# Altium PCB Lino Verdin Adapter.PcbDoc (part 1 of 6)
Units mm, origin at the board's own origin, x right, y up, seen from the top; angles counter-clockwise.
Board outline 69.6 x 35 mm, 8 copper layers (Top Layer, Mid 1, GND 1, Mid 2, Mid 3, GND 2, Mid 4, Bottom Layer), stack 1.198 mm thick; 208 components, 258 nets, 1063 pads, 1090 vias.
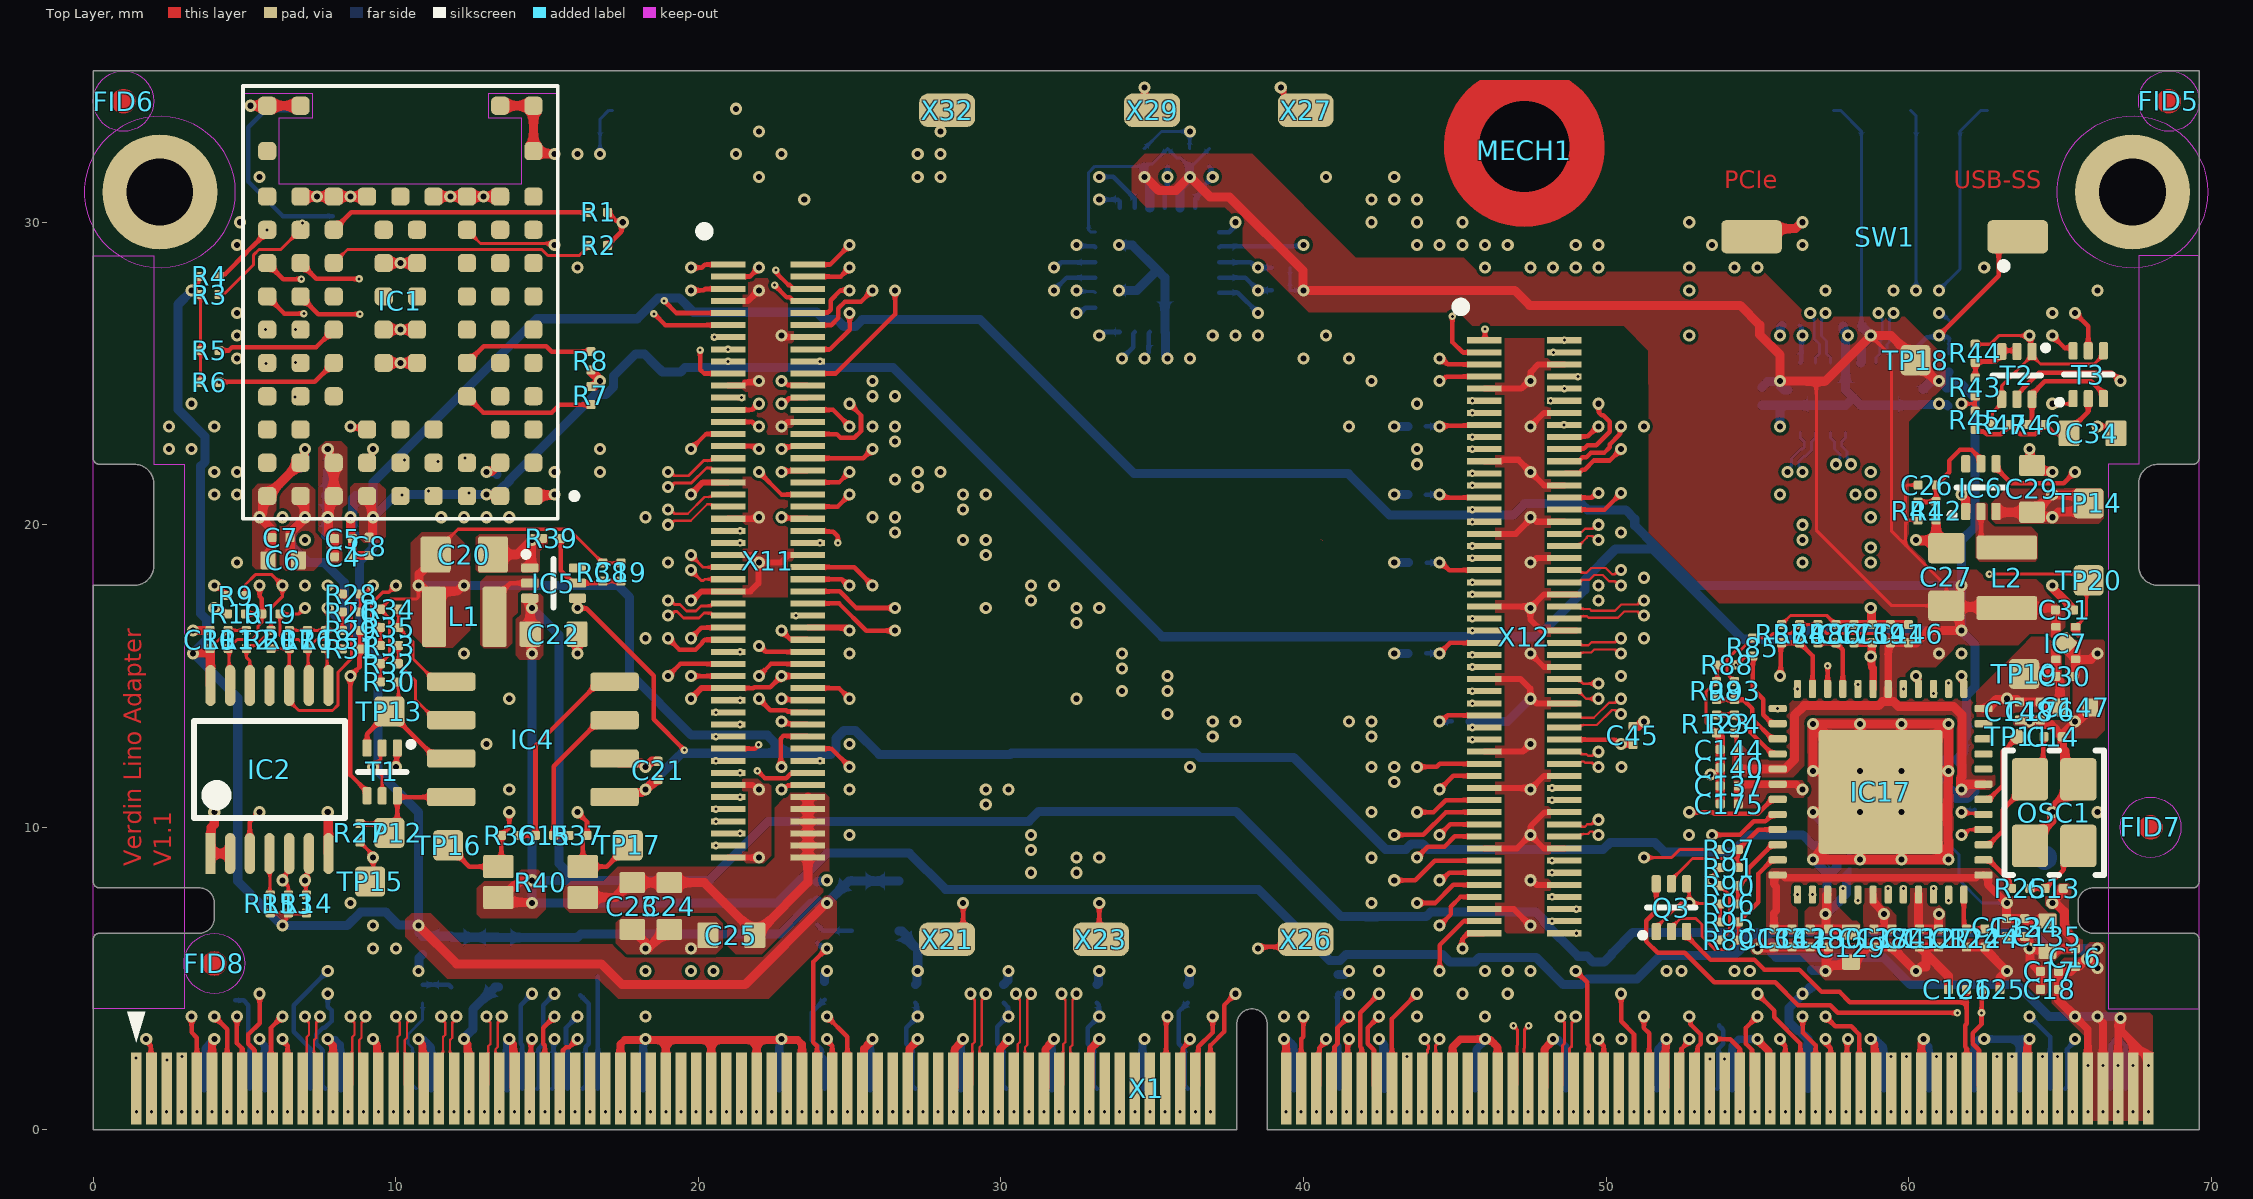
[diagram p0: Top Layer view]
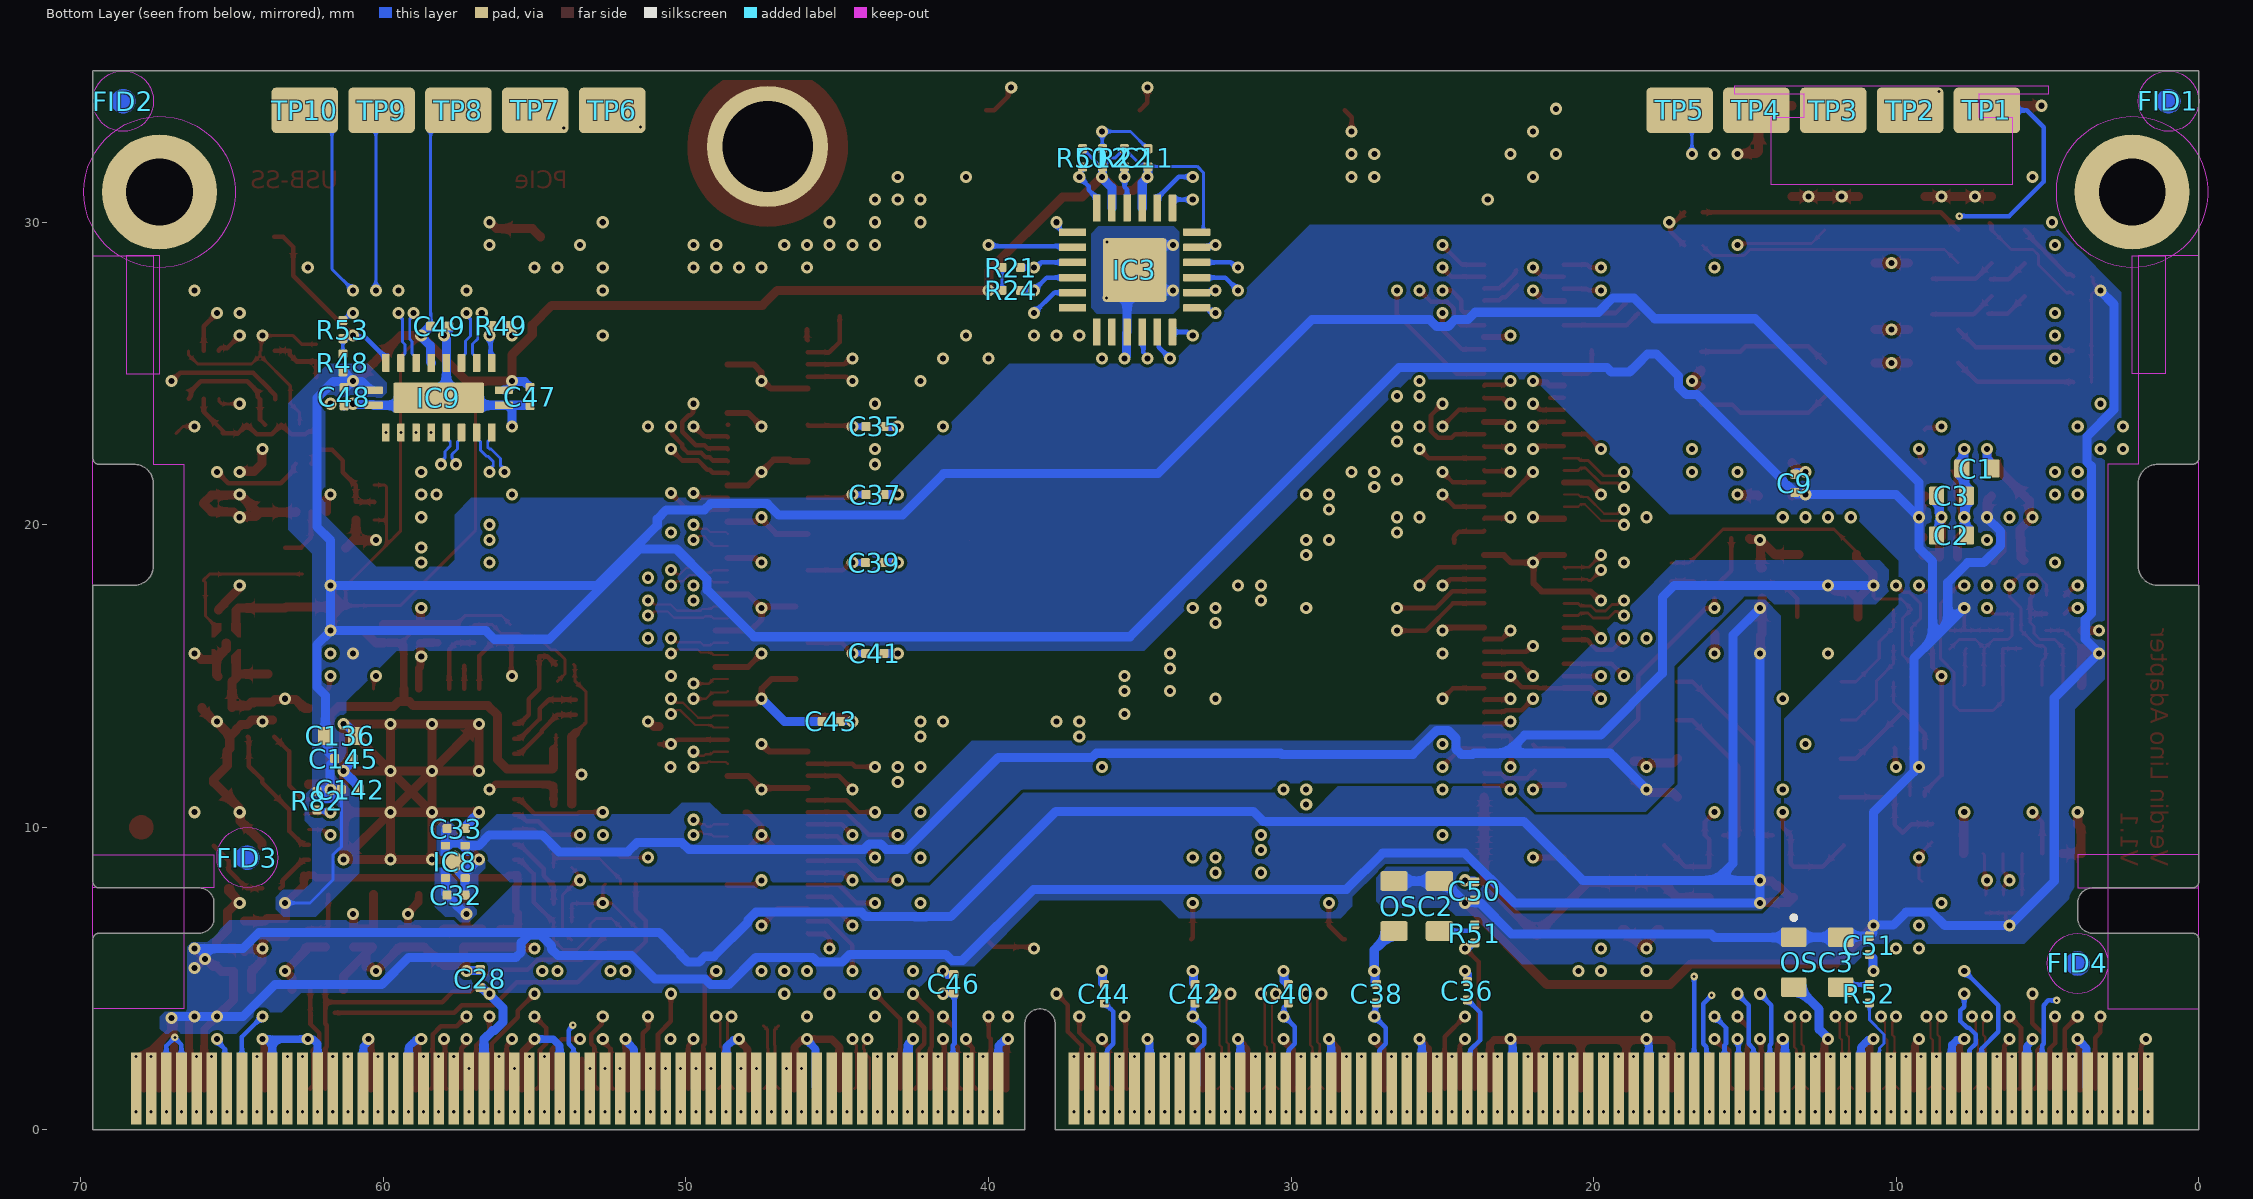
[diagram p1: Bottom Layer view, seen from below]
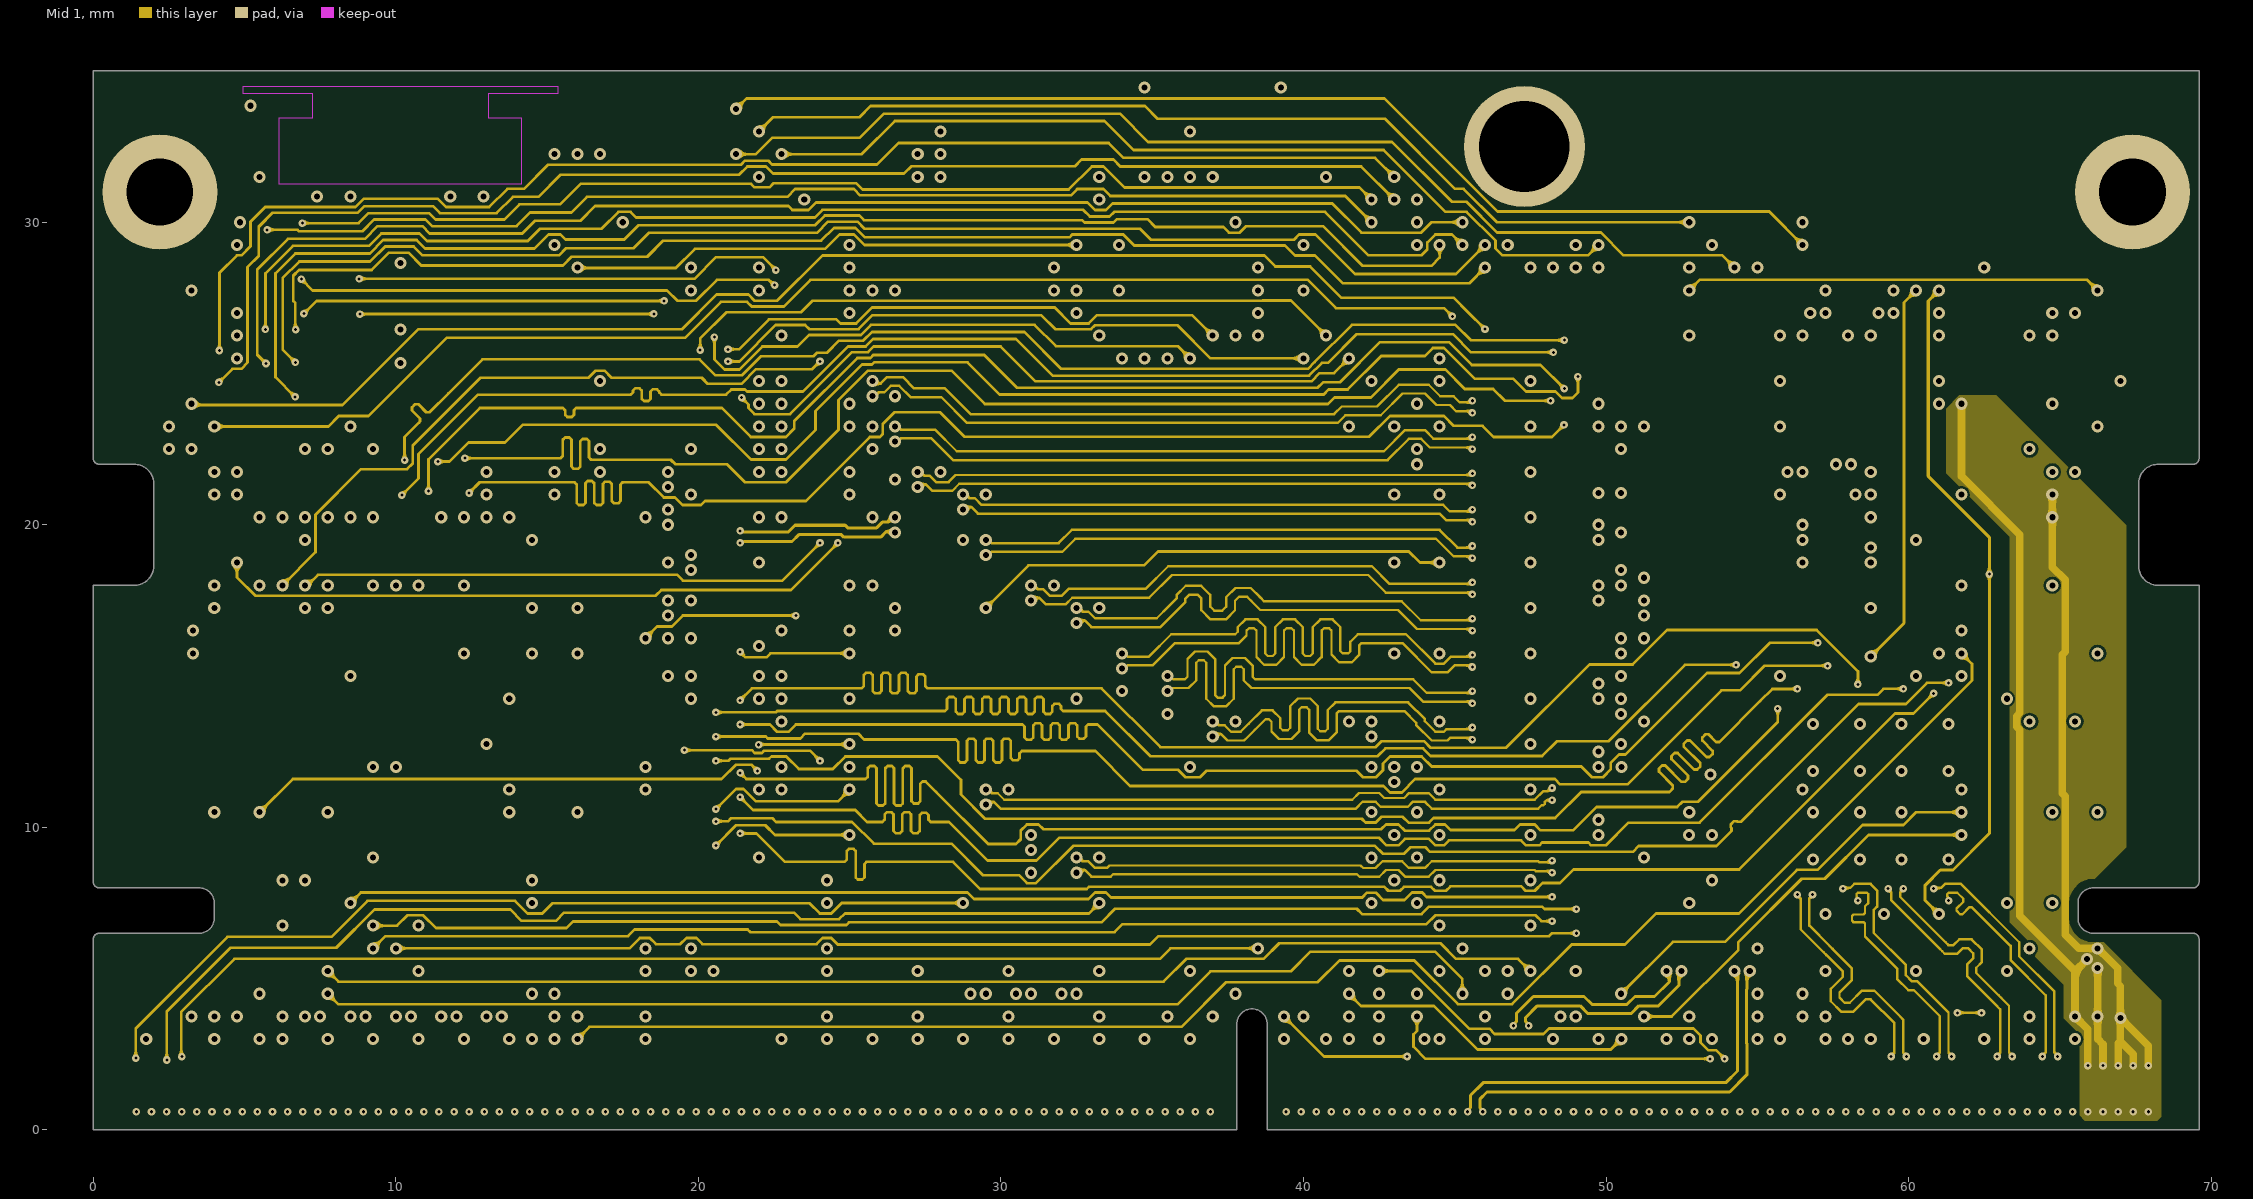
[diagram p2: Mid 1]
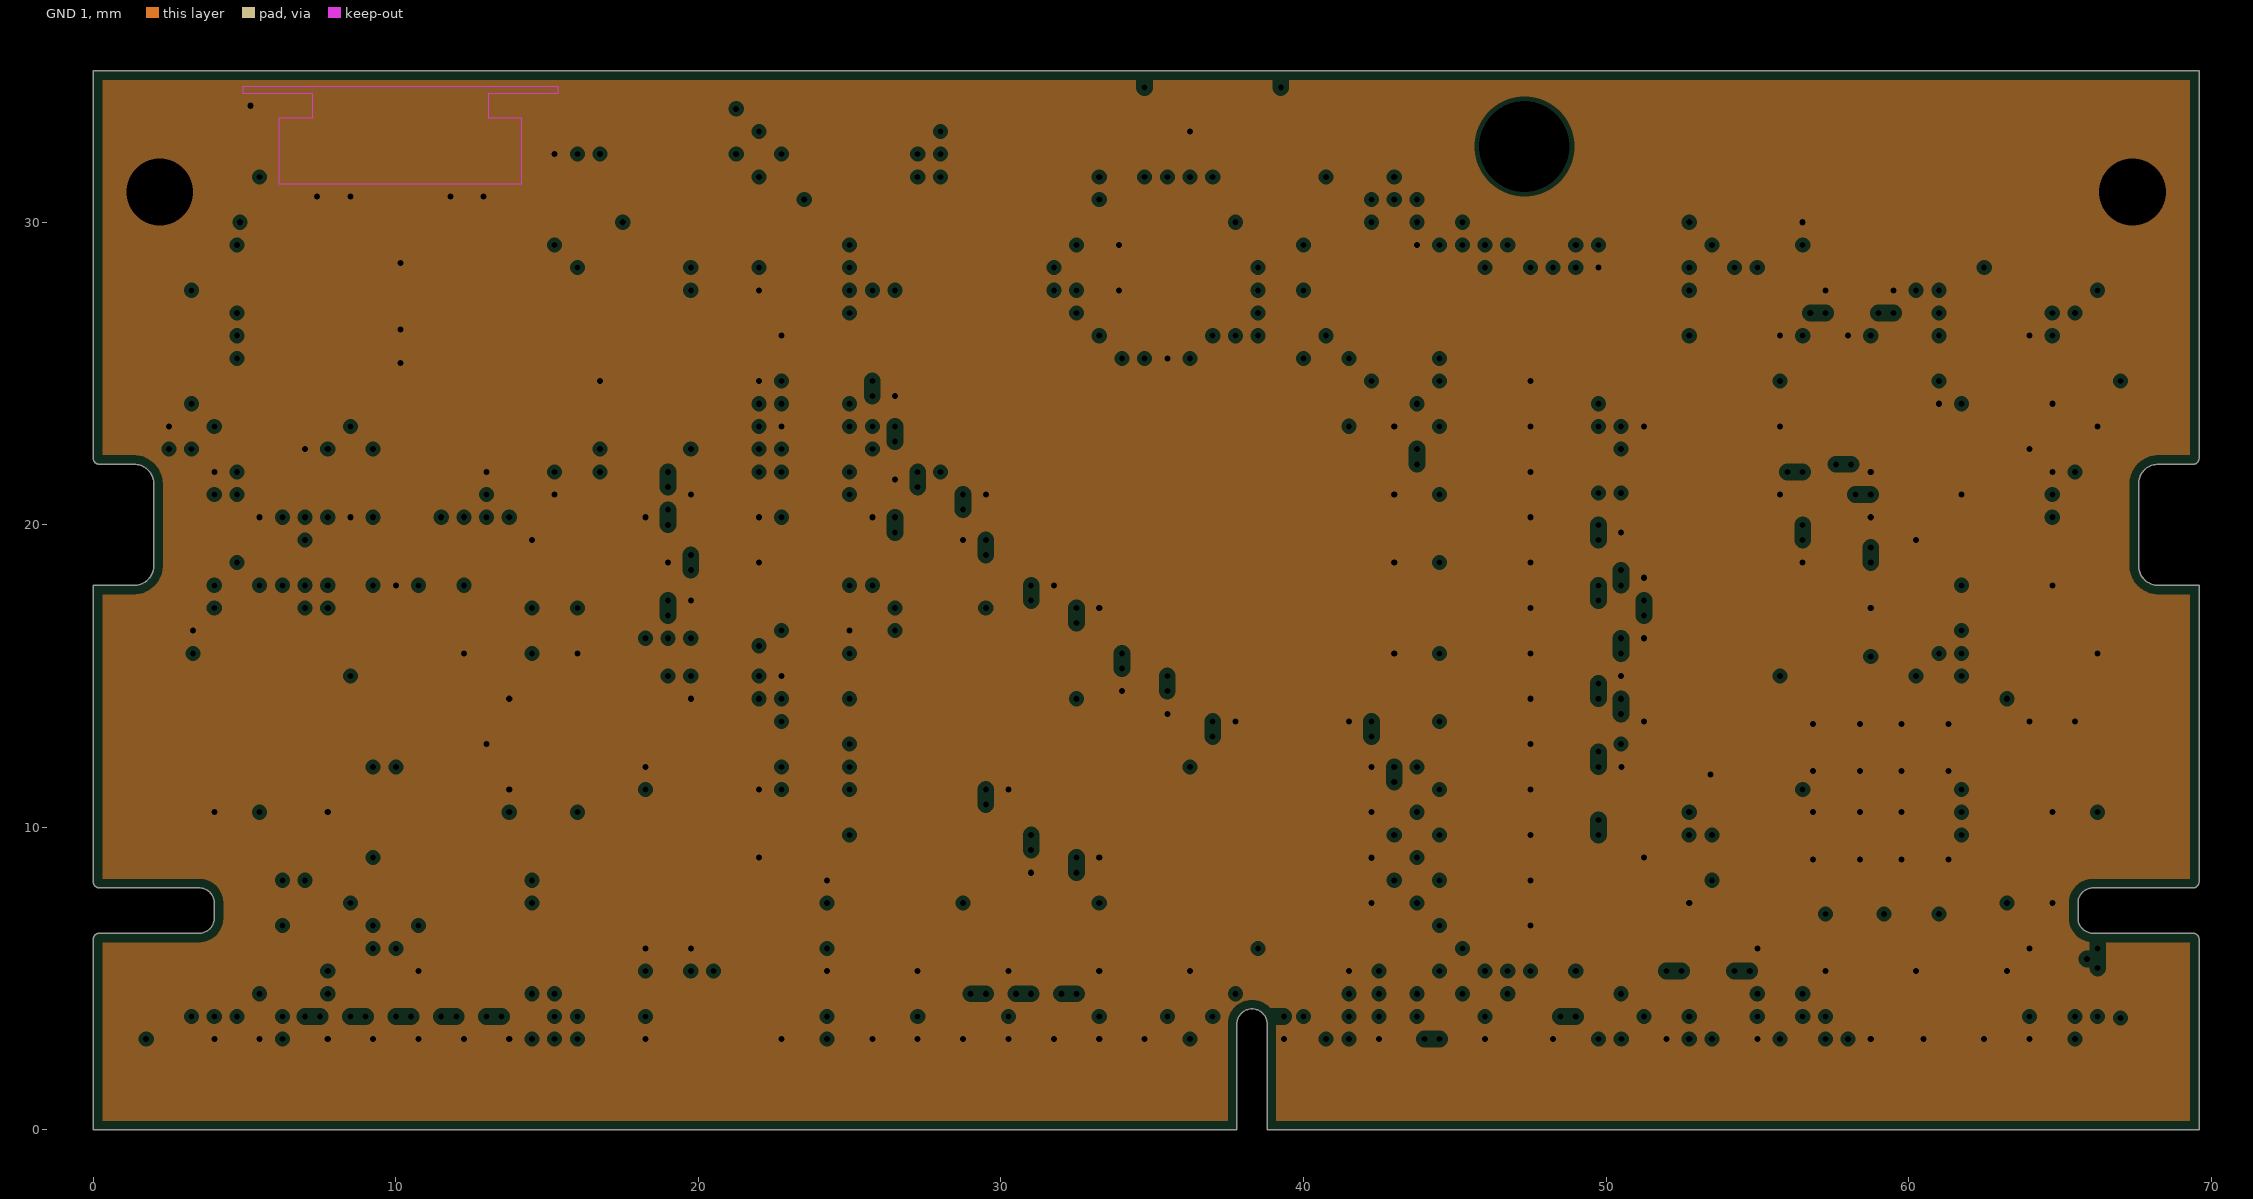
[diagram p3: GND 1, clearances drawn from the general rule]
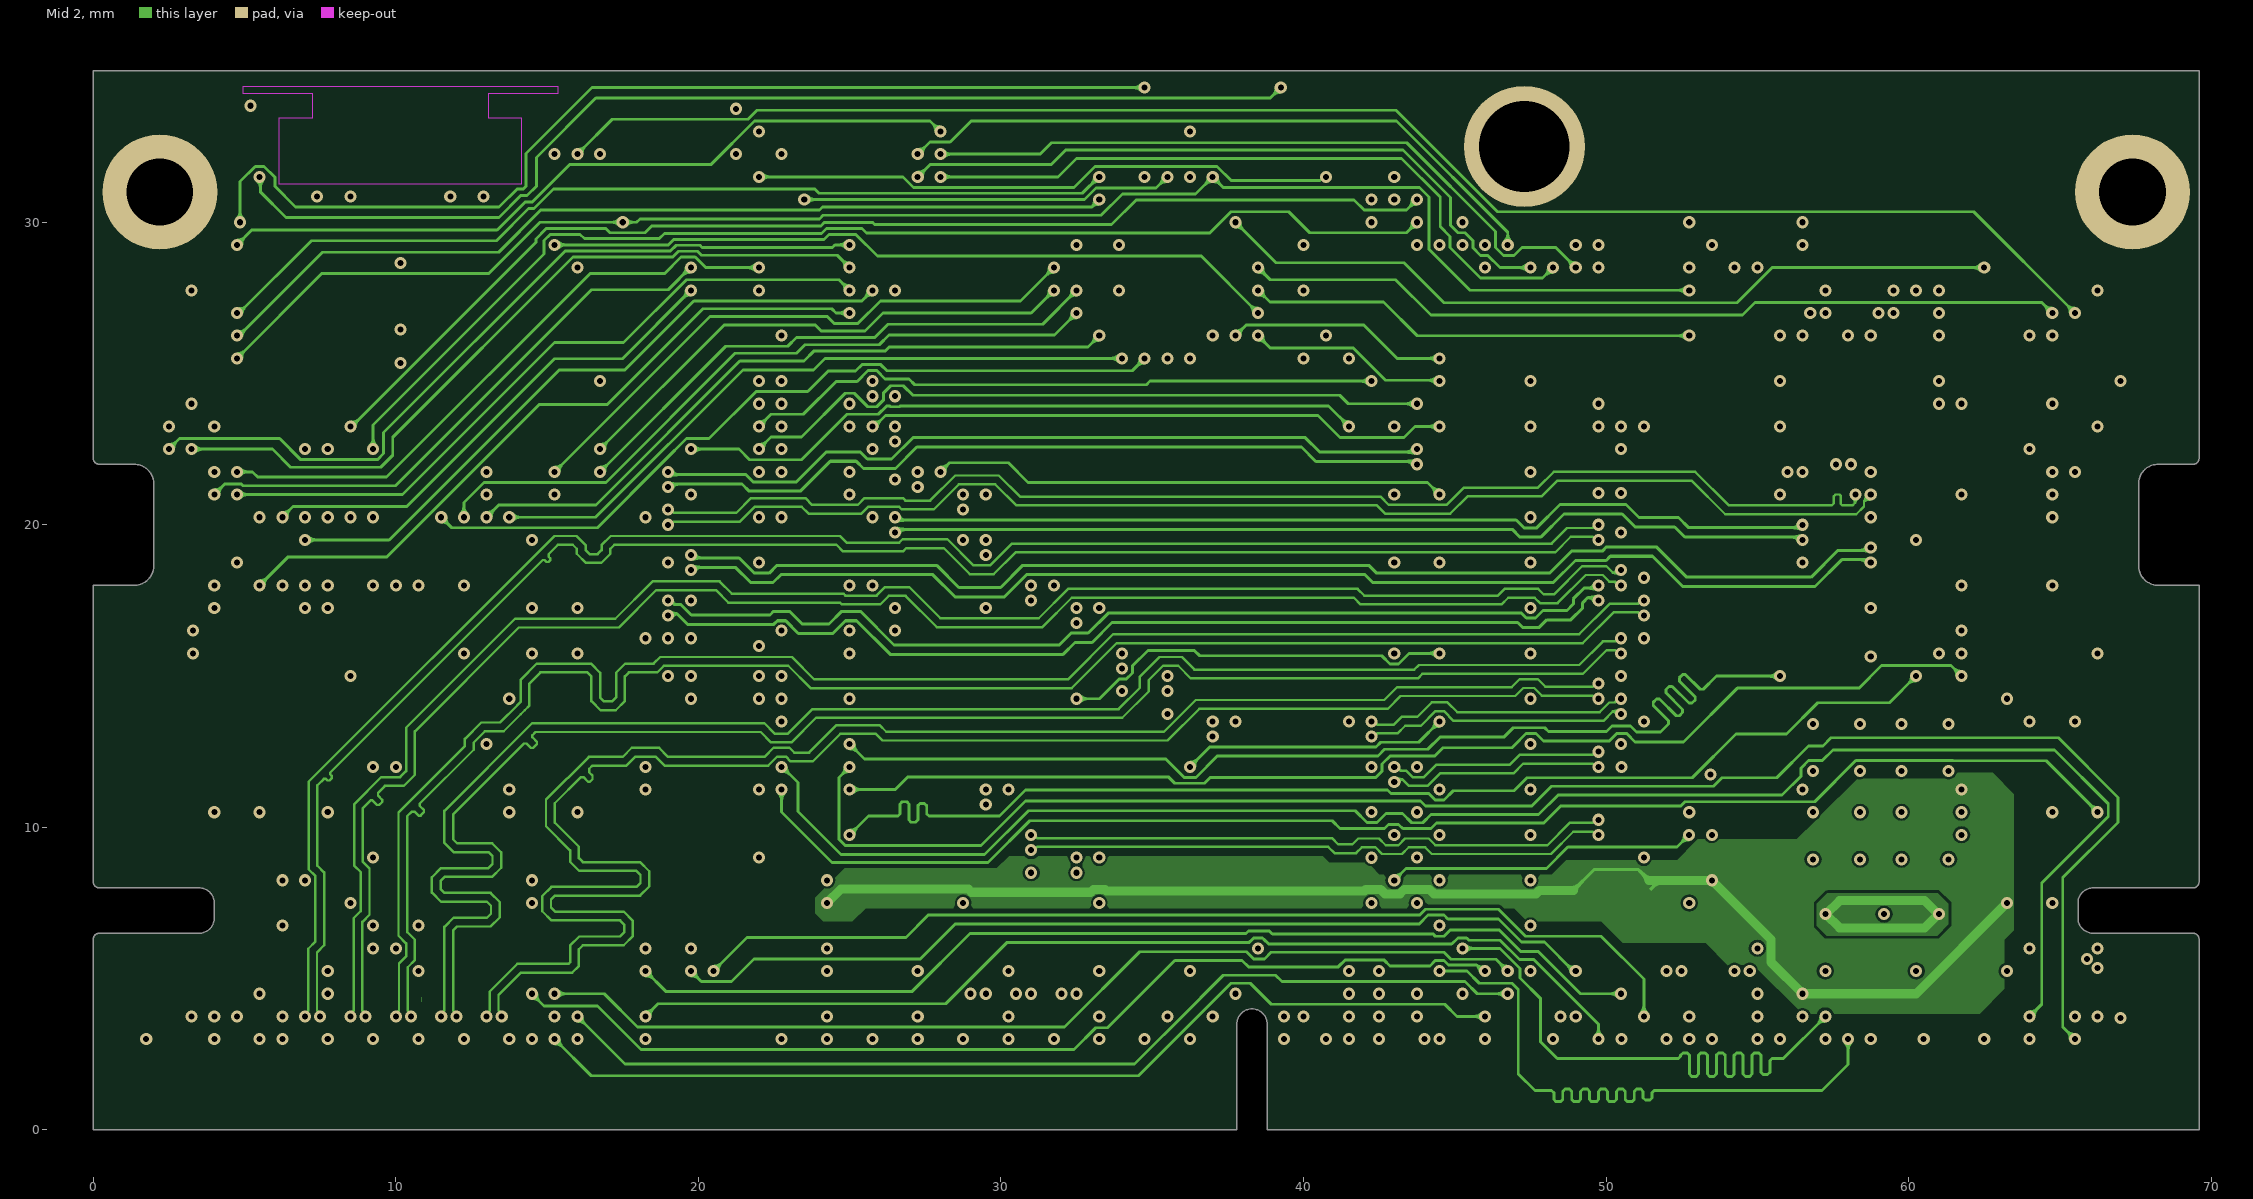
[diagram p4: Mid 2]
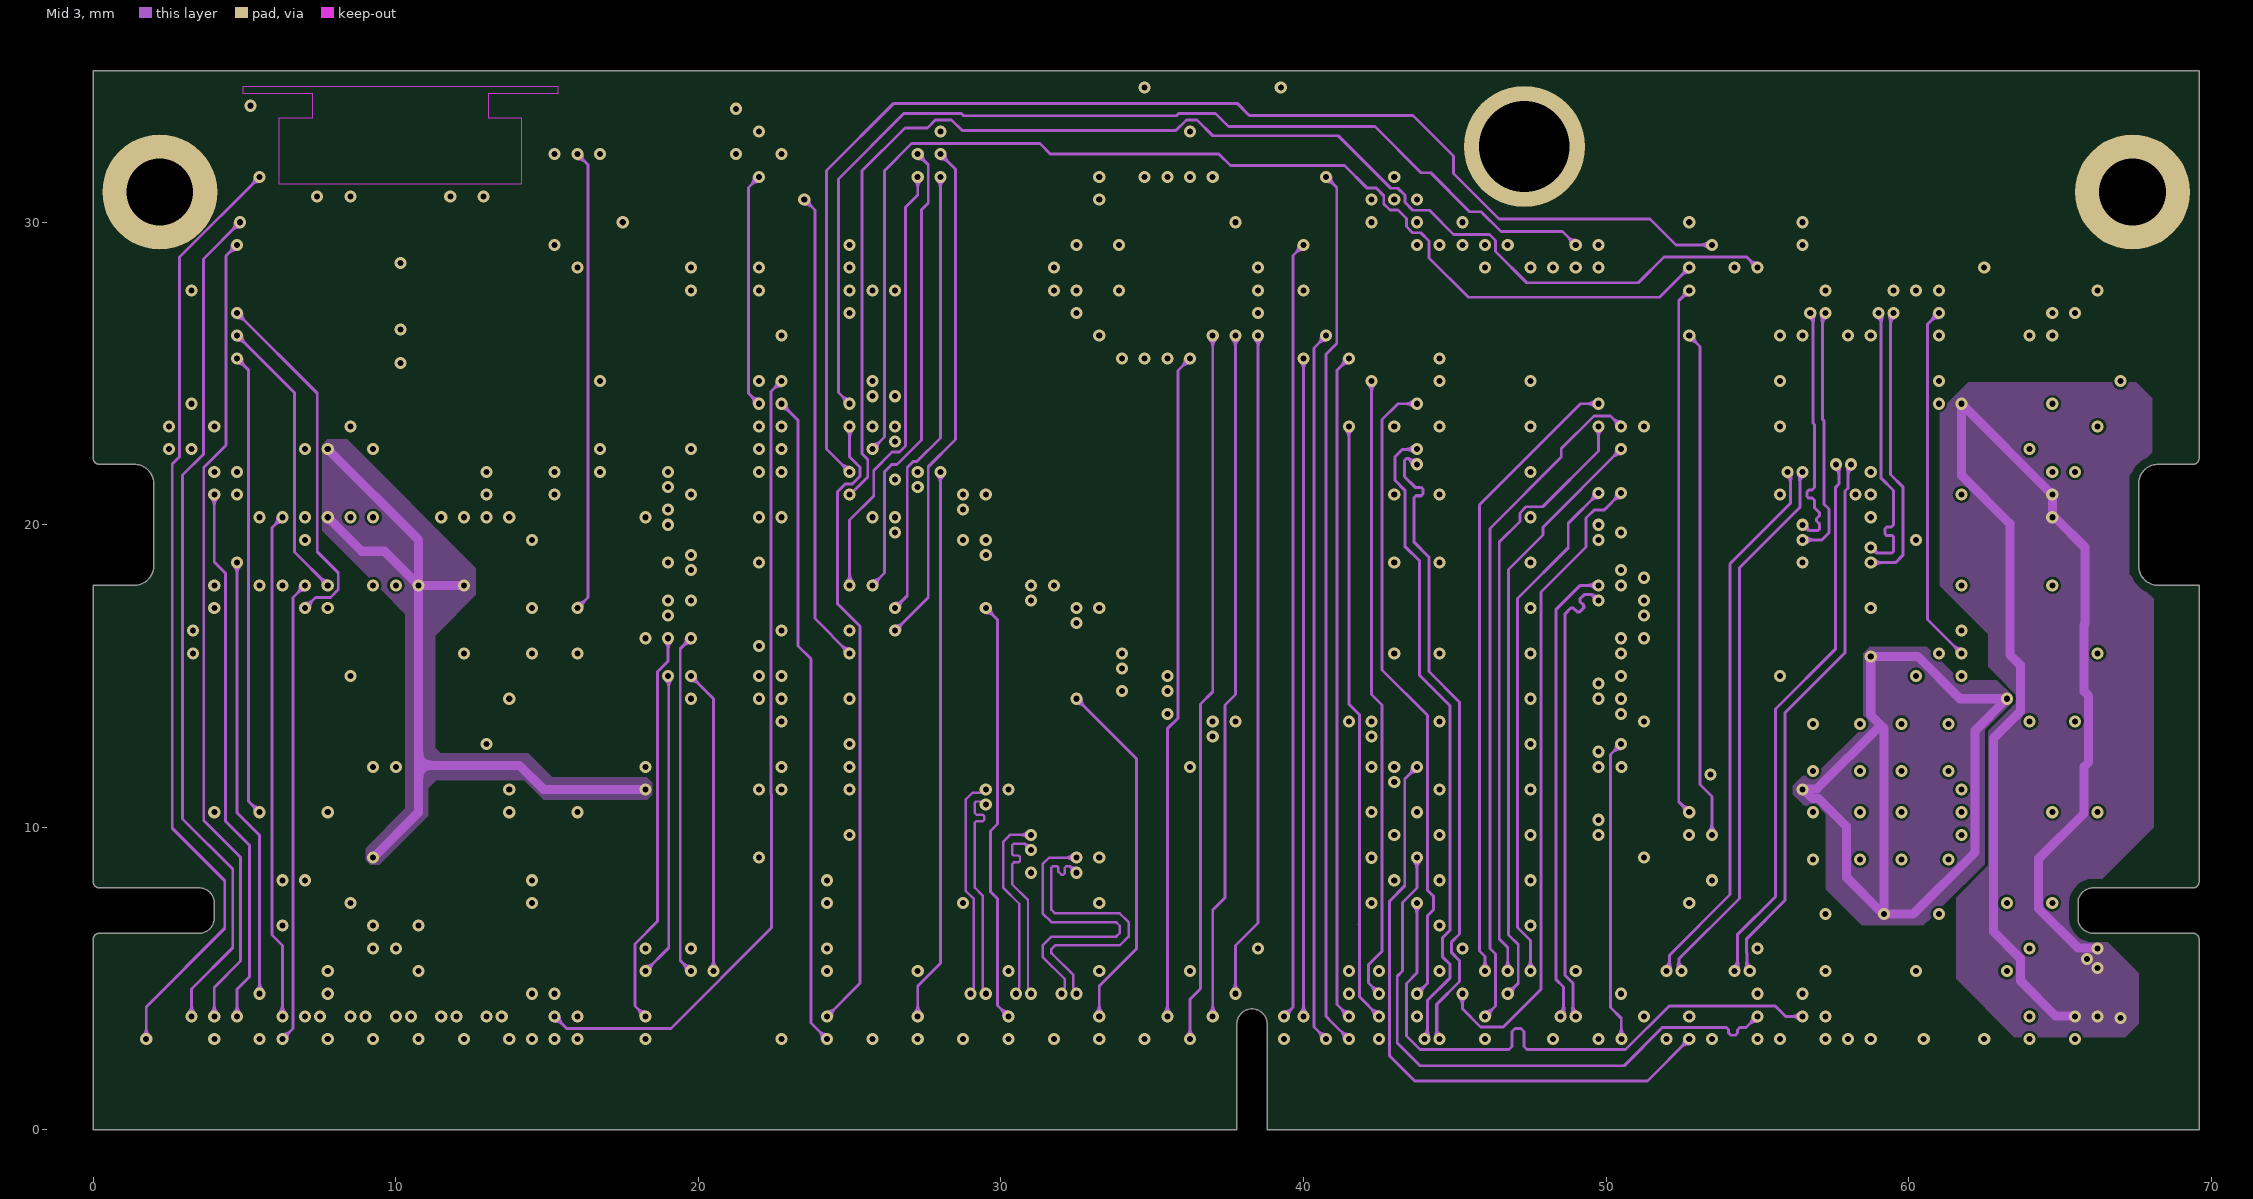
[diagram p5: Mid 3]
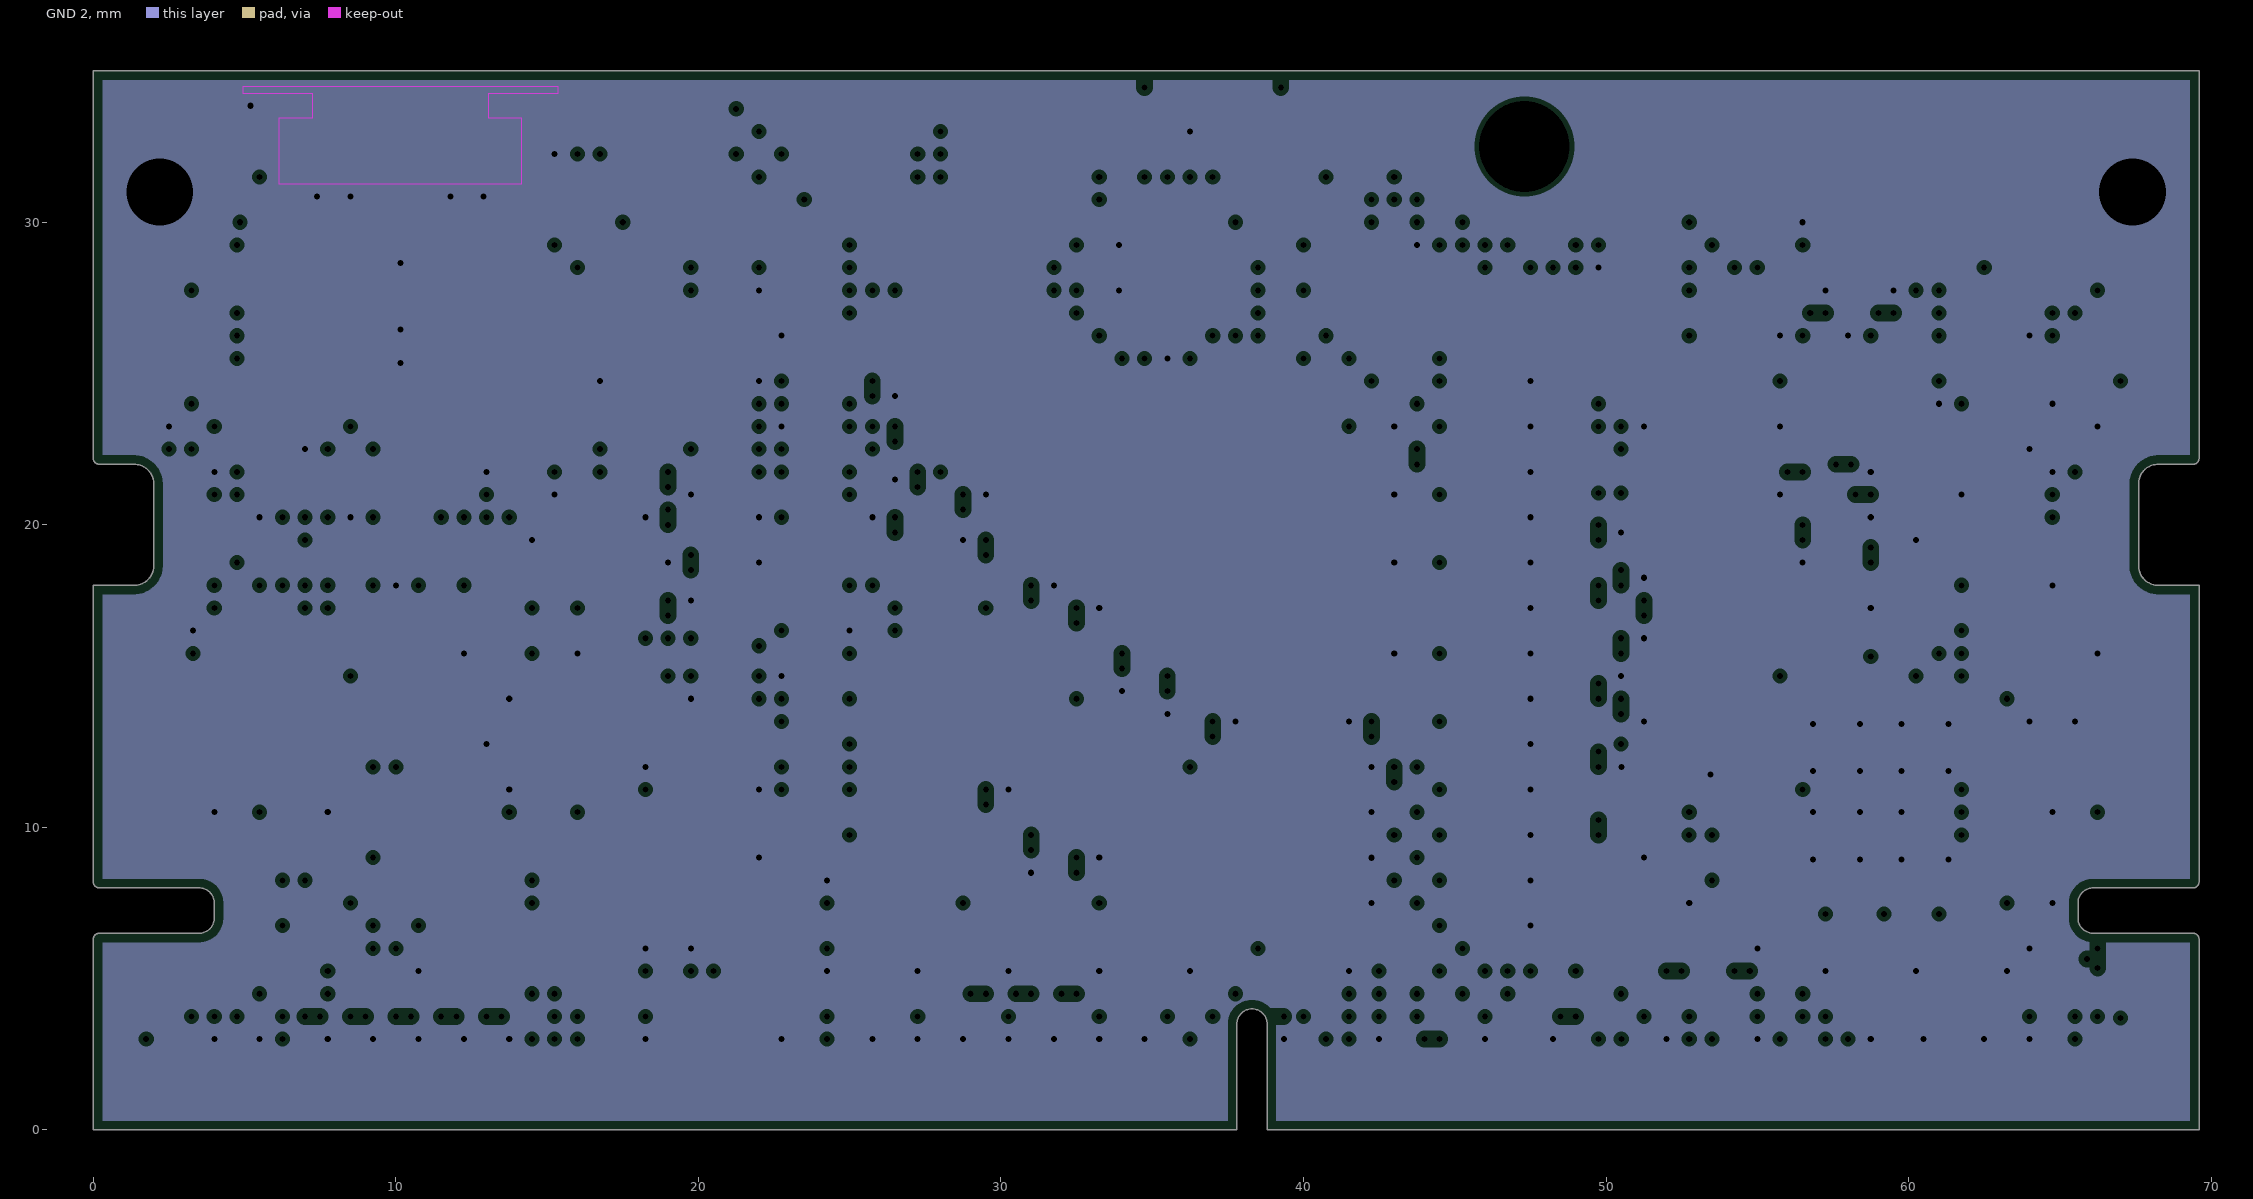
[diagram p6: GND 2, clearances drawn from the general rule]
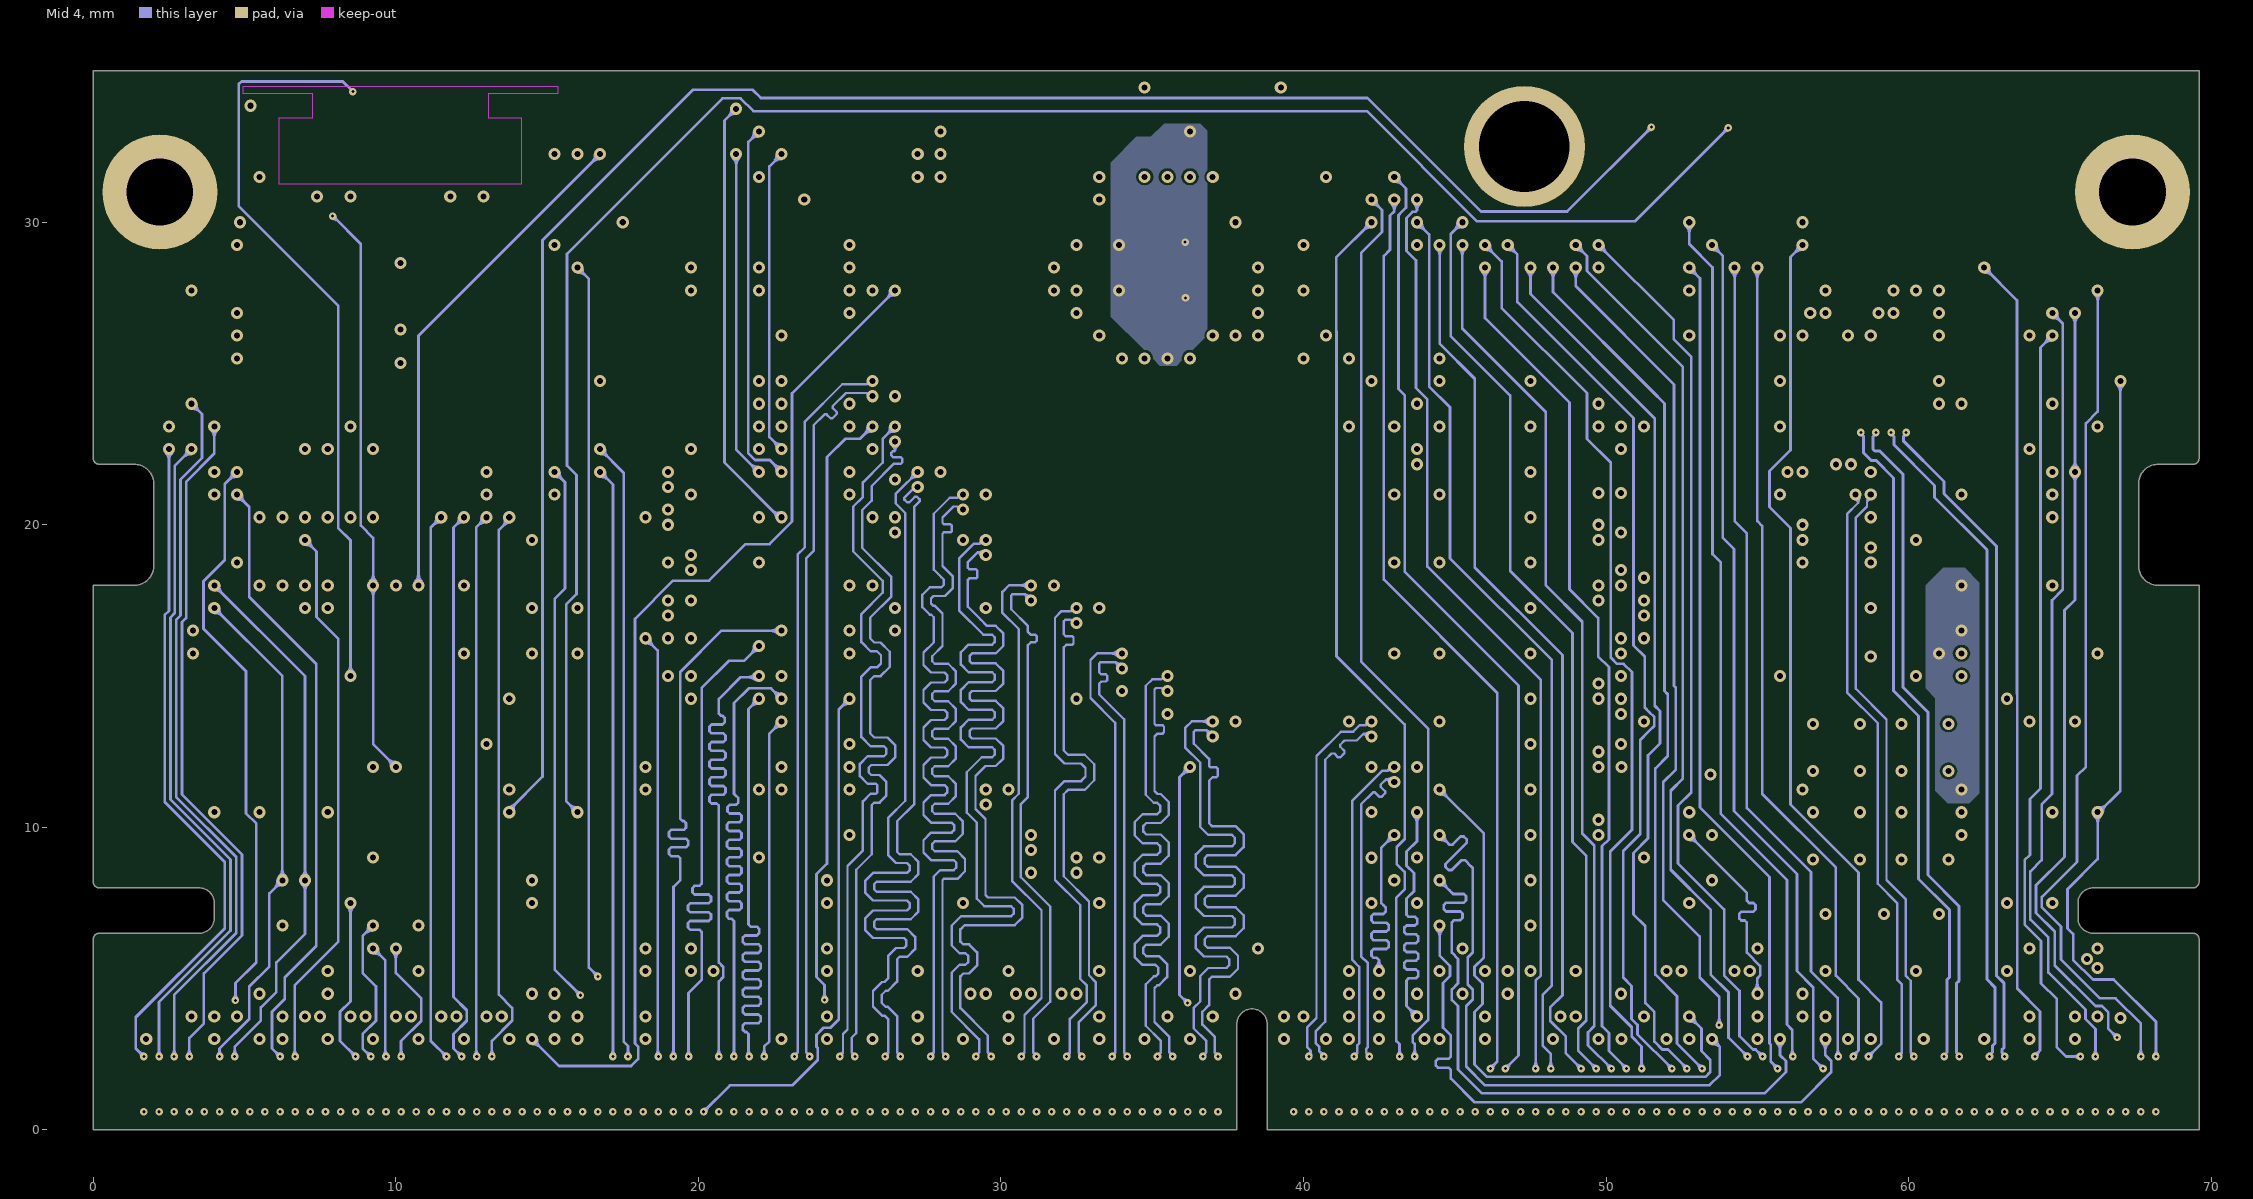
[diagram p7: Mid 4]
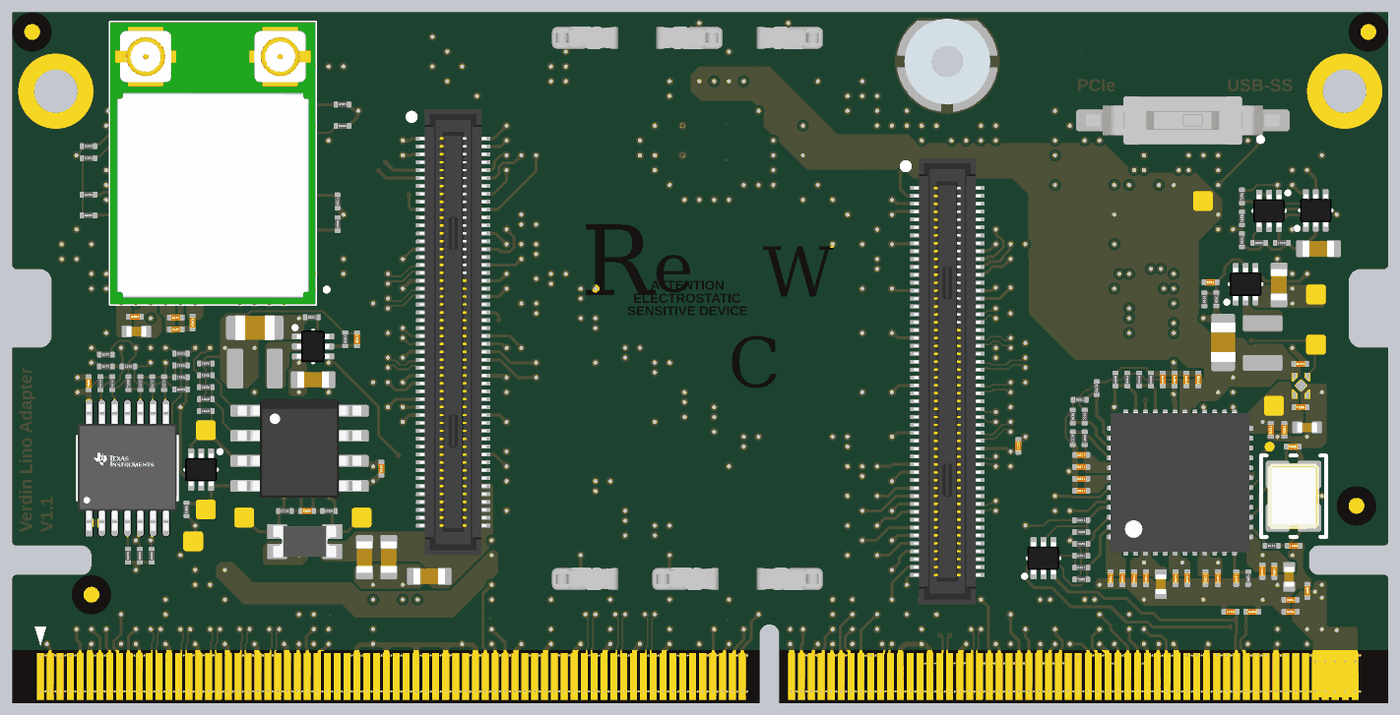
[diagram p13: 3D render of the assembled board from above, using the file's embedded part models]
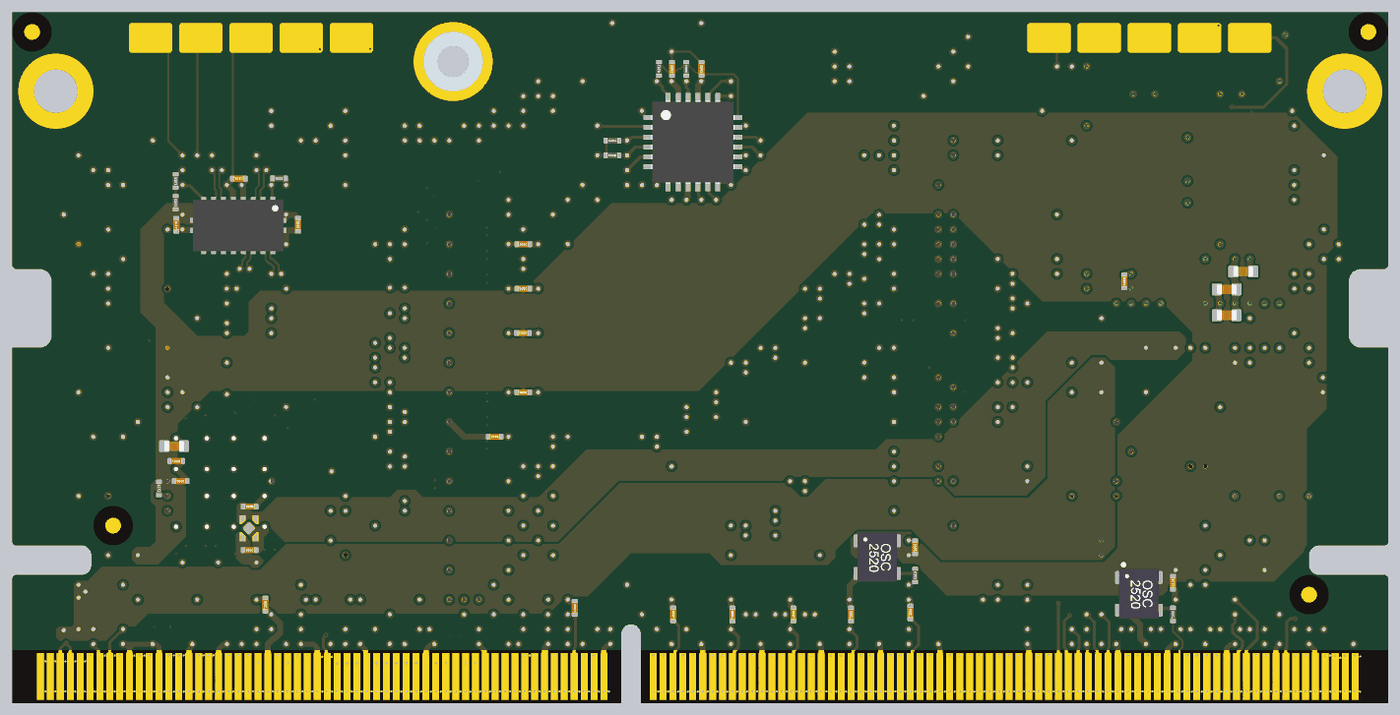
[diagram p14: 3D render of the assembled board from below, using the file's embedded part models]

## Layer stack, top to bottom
Top Solder: solder mask 0.0102, Solder Resist, Dk 3.5
Top Layer: signal copper 0.035
Prepreg 1: prepreg 0.0711, 1080 62%, Dk 4.1
Mid 1: signal copper 0.0175
Core 1: core 0.0635, 1080 62%, Dk 4.2
GND 1: plane copper 0.018, net GND
Prepreg 2: prepreg 0.0711, 1080 62%, Dk 4.1
Mid 2: signal copper 0.018
Core 2: core 0.6096, 3 x 7628 46%, Dk 4.6
Mid 3: signal copper 0.018
Prepreg 3: prepreg 0.0711, 1080 62%, Dk 4.1
GND 2: plane copper 0.018, net GND
Core 3: core 0.0635, 1080 62%, Dk 4.2
Mid 4: signal copper 0.0175
Prepreg 4: prepreg 0.0711, 1080 62%, Dk 4.1
Bottom Layer: signal copper 0.035
Bottom Solder: solder mask 0.0102, Solder Resist, Dk 3.5

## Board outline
0,6.3 cw(c0.2,6.3) 0.2,6.5 3.5,6.5 ccw(c3.5,7) 4,7 4,7.5 ccw(c3.5,7.5) 3.5,8 0.2,8 cw(c0.2,8.2) 0,8.2 0,18 1.35,18 ccw(c1.35,18.65) 2,18.65 2,21.35 ccw(c1.35,21.35) 1.35,22 0.2,22 cw(c0.2,22.2) 0,22.2 0,35 69.6,35 69.6,22.2 cw(c69.4,22.2) 69.4,22 68.25,22 ccw(c68.25,21.35) 67.6,21.35 67.6,18.65 ccw(c68.25,18.65) 68.25,18 69.6,18 69.6,8.2 cw(c69.4,8.2) 69.4,8 66.1,8 ccw(c66.1,7.5) 65.6,7.5 65.6,7 ccw(c66.1,7) 66.1,6.5 69.4,6.5 cw(c69.4,6.3) 69.6,6.3 69.6,0 38.8,0 38.8,3.5 ccw(c38.3,3.5) 37.8,3.5 37.8,0 0,0

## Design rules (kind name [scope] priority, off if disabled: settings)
AssemblyTestPointUsage [All] p1 off:
AssemblyTestpoint [All] p1 off: testpointundercomponent=TRUE minsize=1.016 maxsize=2.54 preferedsize=1.524 minholesize=0 maxholesize=1.016 preferedholesize=0.813 testpointgrid=0.025 usegrid=TRUE gridtolerance=0 allowsidetop=TRUE allowsidebottom=TRUE
BoardOutlineClearance SoDIMM [InComponent('x1')] p1: gap=0.1 ignorepadtopadclearanceinfootprint=FALSE
BoardOutlineClearance [All] p2: gap=0.3 ignorepadtopadclearanceinfootprint=FALSE
Clearance AntiPad [IsThruVia vs OnMid] p1: gap=0.1 ignorepadtopadclearanceinfootprint=FALSE except(0: SMDPad-Hole THPad-Hole Via-Hole Text-Hole; 0.178: Arc-Hole Track-Hole Fill-Hole Poly-Hole Region-Hole)
Clearance SoC_Breakout [OnLayer('Top Layer') vs WithinRoom('Breakout SoC')] p2: gap=0.08 ignorepadtopadclearanceinfootprint=FALSE
Clearance SoC_Breakout_L2 [OnLayer('Mid 1') vs WithinRoom('Breakout SoC')] p3: gap=0.08 ignorepadtopadclearanceinfootprint=FALSE
Clearance SoC_Breakout_Bottom [OnLayer('Bottom Layer') vs WithinRoom('Bottom_Breakout')] p4: gap=0.08 ignorepadtopadclearanceinfootprint=FALSE except(0.1: Arc-THPad Arc-Via Track-THPad Track-Via)
Clearance eMMC_Breakout [OnLayer('Top Layer') vs WithinRoom('Breakout_eMMC_1')] p5: gap=0.078 ignorepadtopadclearanceinfootprint=FALSE
Clearance Clearance_78u_DiffPairs_85 [OnLayer('Int9 (Sign)') or OnLayer('Int2 (SIGN)') vs InNetClass('HS_DIFF_85')] p6 off: gap=0.1 ignorepadtopadclearanceinfootprint=FALSE except(0: Arc-Hole Track-Hole SMDPad-Hole THPad-Hole Via-Hole Fill-Hole Poly-Hole Region-Hole Text-Hole; 0.078: Arc-Arc Arc-Track Track-Track)
Clearance "Clearance Laser Vias" [IsMicroVia] p7: gap=0.1 ignorepadtopadclearanceinfootprint=FALSE except(0: SMDPad-Hole THPad-Hole Via-Hole Text-Hole)
Clearance [All] p8: gap=0.1 ignorepadtopadclearanceinfootprint=FALSE except(0: SMDPad-Hole THPad-Hole Via-Hole Text-Hole; 0.178: Arc-Hole Track-Hole Fill-Hole Poly-Hole Region-Hole)
ComponentClearance "Edge Connector" [InComponent('X1')] p1: gap=0 collisioncheckmode=3 verticalgap=0 showdistances=FALSE
ComponentClearance ComponentClearance_POGOs [(InComponent('x7')OR InComponent('x8')OR InComponent('x9')OR InComponent('x10')OR InComponent('x11')OR InComponent('x12')OR InComponent('x13')OR InComponent('x14')OR InComponent('x15')OR InComponent('x16')OR InComponent('x17')OR InComponent('x18')OR InComponent('x21')OR InComponent('x22')OR InComponent('x23')OR InComponent('x24')OR InComponent('x25')OR InComponent('x26')OR InComponent('x27')OR InComponent('x28')OR InComponent('x29')OR InComponent('x30')OR InComponent('x32')OR InComponent('x33')OR InComponent('x34')OR InComponent('x37')OR InComponent('x38'))] p2 off: gap=0.14 collisioncheckmode=3 verticalgap=0.254 showdistances=FALSE
ComponentClearance [All] p3: gap=0.1 collisioncheckmode=3 verticalgap=0.5 showdistances=TRUE
DiffPairsRouting DiffPairs_Breakout_100 [WithinRoom('Breakout SoC') and (OnLayer('Top Layer')  or OnLayer('Mid 1'))and InNetClass('HS_DIFF_100')] p1: maxlimit=0.162 minlimit=0.08 mostfreqgap=0.126 toplayer_prefgap=0.162 toplayer_minwidth=0.075 toplayer_maxwidth=0.075 toplayer_prefwidth=0.075 midlayer1_mingap=0.126 midlayer1_maxgap=0.126 midlayer1_minwidth=0.079 midlayer1_maxwidth=0.08 midlayer1_prefwidth=0.08 midlayer2_mingap=0.112 midlayer2_maxgap=0.112 midlayer2_prefgap=0.112 midlayer2_minwidth=0.064 midlayer2_maxwidth=0.08 midlayer2_prefwidth=0.08 midlayer4_mingap=0.126 midlayer4_maxgap=0.126 midlayer4_minwidth=0.079 midlayer4_maxwidth=0.08 midlayer4_prefwidth=0.08 midlayer5_mingap=0.1 midlayer5_maxgap=0.12 midlayer5_prefgap=0.1 midlayer5_minwidth=0.08 midlayer5_maxwidth=0.1 midlayer5_prefwidth=0.08 bottomlayer_mingap=0.162 bottomlayer_prefgap=0.162 bottomlayer_minwidth=0.075 bottomlayer_maxwidth=0.075 bottomlayer_prefwidth=0.075 maxuncoupledlength=12.7
DiffPairsRouting DiffPairs_Breakout_90 [WithinRoom('Breakout SoC') and (OnLayer('Top Layer')  or OnLayer('Mid 1')) and InNetClass('HS_DIFF_90')] p2: maxlimit=0.143 minlimit=0.08 mostfreqgap=0.112 toplayer_prefgap=0.143 toplayer_minwidth=0.08 toplayer_maxwidth=0.095 toplayer_prefwidth=0.095 midlayer1_mingap=0.112 midlayer1_maxgap=0.112 midlayer1_minwidth=0.098 midlayer1_maxwidth=0.098 midlayer1_prefwidth=0.098 midlayer2_mingap=0.109 midlayer2_maxgap=0.109 midlayer2_prefgap=0.109 midlayer2_minwidth=0.082 midlayer2_maxwidth=0.082 midlayer2_prefwidth=0.082 midlayer4_mingap=0.112 midlayer4_maxgap=0.112 midlayer4_minwidth=0.098 midlayer4_maxwidth=0.098 midlayer4_prefwidth=0.098 midlayer5_mingap=0.1 midlayer5_maxgap=0.1 midlayer5_prefgap=0.1 midlayer5_minwidth=0.08 midlayer5_maxwidth=0.1 midlayer5_prefwidth=0.1 bottomlayer_mingap=0.143 bottomlayer_prefgap=0.143 bottomlayer_minwidth=0.095 bottomlayer_maxwidth=0.095 bottomlayer_prefwidth=0.095 maxuncoupledlength=12.7
DiffPairsRouting DiffPairs_Breakout_80 [WithinRoom('Breakout SoC') and (OnLayer('Top Layer') or OnLayer('Mid 1')) and InNetClass('HS_DIFF_80')] p3: maxlimit=0.104 minlimit=0.078 mostfreqgap=0.082 toplayer_mingap=0.08 toplayer_prefgap=0.104 toplayer_minwidth=0.08 toplayer_maxwidth=0.095 toplayer_prefwidth=0.095 midlayer1_mingap=0.082 midlayer1_maxgap=0.082 midlayer1_minwidth=0.098 midlayer1_maxwidth=0.098 midlayer1_prefwidth=0.098 midlayer2_maxgap=0.078 midlayer2_prefgap=0.078 midlayer2_minwidth=0.082 midlayer2_maxwidth=0.082 midlayer2_prefwidth=0.082 midlayer4_mingap=0.082 midlayer4_maxgap=0.082 midlayer4_minwidth=0.098 midlayer4_maxwidth=0.13 midlayer4_prefwidth=0.098 midlayer5_mingap=0.1 midlayer5_maxgap=0.1 midlayer5_prefgap=0.1 midlayer5_minwidth=0.08 midlayer5_maxwidth=0.13 midlayer5_prefwidth=0.1 bottomlayer_mingap=0.104 bottomlayer_prefgap=0.104 bottomlayer_minwidth=0.095 bottomlayer_maxwidth=0.095 bottomlayer_prefwidth=0.095 maxuncoupledlength=12.7
DiffPairsRouting DiffPairsRouting_100 [InNetClass('HS_DIFF_100')] p4: maxlimit=0.21 minlimit=0.162 mostfreqgap=0.21 toplayer_maxgap=0.162 toplayer_prefgap=0.162 toplayer_minwidth=0.075 toplayer_maxwidth=0.075 toplayer_prefwidth=0.075 midlayer1_mingap=0.21 midlayer1_minwidth=0.08 midlayer1_maxwidth=0.08 midlayer1_prefwidth=0.08 midlayer2_mingap=0.21 midlayer2_minwidth=0.08 midlayer2_maxwidth=0.08 midlayer2_prefwidth=0.08 midlayer4_mingap=0.21 midlayer4_minwidth=0.08 midlayer4_maxwidth=0.08 midlayer4_prefwidth=0.08 midlayer5_mingap=0.21 midlayer5_minwidth=0.08 midlayer5_maxwidth=0.08 midlayer5_prefwidth=0.08 bottomlayer_maxgap=0.162 bottomlayer_prefgap=0.162 bottomlayer_minwidth=0.075 bottomlayer_maxwidth=0.075 bottomlayer_prefwidth=0.075 maxuncoupledlength=12.7
DiffPairsRouting DiffPairsRouting_90 [InNetClass('HS_DIFF_90')] p5: maxlimit=0.21 minlimit=0.143 mostfreqgap=0.21 toplayer_maxgap=0.143 toplayer_prefgap=0.143 toplayer_minwidth=0.095 toplayer_maxwidth=0.095 toplayer_prefwidth=0.095 midlayer1_mingap=0.21 midlayer1_minwidth=0.1 midlayer1_maxwidth=0.1 midlayer1_prefwidth=0.1 midlayer2_mingap=0.21 midlayer2_minwidth=0.1 midlayer2_maxwidth=0.1 midlayer2_prefwidth=0.1 midlayer4_mingap=0.21 midlayer4_minwidth=0.1 midlayer4_maxwidth=0.1 midlayer4_prefwidth=0.1 midlayer5_mingap=0.21 midlayer5_minwidth=0.1 midlayer5_maxwidth=0.1 midlayer5_prefwidth=0.1 bottomlayer_maxgap=0.143 bottomlayer_prefgap=0.143 bottomlayer_minwidth=0.095 bottomlayer_maxwidth=0.095 bottomlayer_prefwidth=0.095 maxuncoupledlength=12.7
DiffPairsRouting DiffPairsRouting_80 [InNetClass('HS_DIFF_80')] p6: maxlimit=0.21 minlimit=0.104 mostfreqgap=0.21 toplayer_maxgap=0.104 toplayer_prefgap=0.104 toplayer_minwidth=0.095 toplayer_maxwidth=0.3 toplayer_prefwidth=0.095 midlayer1_mingap=0.21 midlayer1_minwidth=0.13 midlayer1_maxwidth=0.13 midlayer1_prefwidth=0.13 midlayer2_mingap=0.21 midlayer2_minwidth=0.13 midlayer2_maxwidth=0.13 midlayer2_prefwidth=0.13 midlayer4_mingap=0.21 midlayer4_minwidth=0.13 midlayer4_maxwidth=0.13 midlayer4_prefwidth=0.13 midlayer5_mingap=0.21 midlayer5_minwidth=0.13 midlayer5_maxwidth=0.13 midlayer5_prefwidth=0.13 bottomlayer_maxgap=0.104 bottomlayer_prefgap=0.104 bottomlayer_minwidth=0.095 bottomlayer_maxwidth=0.3 bottomlayer_prefwidth=0.095 maxuncoupledlength=12.7
DiffPairsRouting [All] p7 off: maxlimit=0.224 minlimit=0.162 mostfreqgap=0.21 toplayer_prefgap=0.162 toplayer_minwidth=0.075 toplayer_maxwidth=0.081 toplayer_prefwidth=0.075 midlayer1_mingap=0.21 midlayer1_maxgap=0.21 midlayer1_minwidth=0.1 midlayer1_maxwidth=0.1 midlayer1_prefwidth=0.1 midlayer2_mingap=0.21 midlayer2_maxgap=0.21 midlayer2_minwidth=0.1 midlayer2_maxwidth=0.1 midlayer2_prefwidth=0.1 midlayer4_mingap=0.21 midlayer4_maxgap=0.21 midlayer4_minwidth=0.1 midlayer4_maxwidth=0.1 midlayer4_prefwidth=0.1 midlayer5_mingap=0.21 midlayer5_maxgap=0.21 midlayer5_minwidth=0.1 midlayer5_maxwidth=0.1 midlayer5_prefwidth=0.1 bottomlayer_prefgap=0.162 bottomlayer_minwidth=0.075 bottomlayer_maxwidth=0.081 bottomlayer_prefwidth=0.075 maxuncoupledlength=12.7
FabricationTestPointUsage TestPointUsage [All] p1 off: valid=0 allowmultiple=FALSE
FabricationTestpoint Testpoint [All] p1 off: side=3 testpointundercomponent=TRUE minsize=1.016 maxsize=2.54 preferedsize=1.524 minholesize=0 maxholesize=1.016 preferedholesize=0.813 testpointgrid=0.025 allowsidetop=TRUE allowsidebottom=TRUE usegrid=TRUE gridtolerance=0
FanoutControl Fanout_BGA [IsBGA] p1 off: bgadir=Out bgaviamode=Centered fanoutstyle=BGA fanoutdirection=Alternating viagrid=0.025 // Fanout_BGA (Default Rule)
FanoutControl Fanout_LCC [IsLCC] p2 off: bgadir=Out bgaviamode=Centered fanoutstyle=Auto fanoutdirection=Alternating viagrid=0.025 // Fanout_LCC (Default Rule)
FanoutControl Fanout_SOIC [IsSOIC] p3 off: bgadir=Out bgaviamode=Centered fanoutstyle=Auto fanoutdirection=Alternating viagrid=0.025 // Fanout_SOIC (Default Rule)
FanoutControl Fanout_Small [(CompPinCount < 5)] p4 off: bgadir=Out bgaviamode=Centered fanoutstyle=Auto fanoutdirection=OutThenIn viagrid=0.025 // Fanout_Small (Default Rule)
FanoutControl Fanout_Default [All] p5 off: bgadir=Out bgaviamode=Centered fanoutstyle=Auto fanoutdirection=Alternating viagrid=0.025 // Fanout_Default (Default Rule)
Height [All] p1: minheight=0 maxheight=40 prefheight=12.7
HoleSize [All] p1: absolutevalues=TRUE maxlimit=5 minlimit=0.025 maxpercent=80.000 minpercent=20.000
HoleToHoleClearance "Via Stackup Clearance" [IsMicroVia vs IsBuriedVia] p1: gap=0.165 allowstackedmicrovias=FALSE
HoleToHoleClearance [All] p2: gap=0.2 allowstackedmicrovias=FALSE
MatchedLengths "SD Card" [InNetClass('SD_Card')] p1: tolerance=3 checknetsindiffpair=FALSE checkdiffpairvsdiffpair=TRUE checkxsignals=TRUE checkothers=TRUE
MatchedLengths "WiFi SDIO" [InNetClass('WiFi_SDIO')] p2: tolerance=3 checknetsindiffpair=FALSE checkdiffpairvsdiffpair=TRUE checkxsignals=TRUE checkothers=TRUE
MatchedLengths Diff_Pair_PCIe [InNetClass('PCIe')] p3: tolerance=0.06 checknetsindiffpair=TRUE checkdiffpairvsdiffpair=FALSE checkxsignals=FALSE checkothers=FALSE
MatchedLengths Diff_Pair_ETH [InNetClass('ETH_DIFF')] p4: tolerance=0.25 checknetsindiffpair=TRUE checkdiffpairvsdiffpair=FALSE checkxsignals=FALSE checkothers=FALSE
MatchedLengths Diff_Pair_100R [InNetClass('HS_DIFF_100')] p5: tolerance=0.15 checknetsindiffpair=TRUE checkdiffpairvsdiffpair=FALSE checkxsignals=FALSE checkothers=FALSE
MatchedLengths Diff_Pair_90R [InNetClass('HS_DIFF_90')] p6: tolerance=0.15 checknetsindiffpair=TRUE checkdiffpairvsdiffpair=FALSE checkxsignals=FALSE checkothers=FALSE
MatchedLengths DSI [InNetClass('DSI')] p7: tolerance=1.5 checknetsindiffpair=FALSE checkdiffpairvsdiffpair=TRUE checkxsignals=TRUE checkothers=TRUE
MatchedLengths CSI_1 [InNetClass('CSI_1')] p8: tolerance=1.5 checknetsindiffpair=FALSE checkdiffpairvsdiffpair=TRUE checkxsignals=TRUE checkothers=TRUE
MatchedLengths LVDS [InNetClass('LVDS')] p9: tolerance=0.5 checknetsindiffpair=FALSE checkdiffpairvsdiffpair=TRUE checkxsignals=TRUE checkothers=TRUE
MatchedLengths MSP [InNetClass('MSP_DIFF')] p10 off: tolerance=1.5 checknetsindiffpair=FALSE checkdiffpairvsdiffpair=TRUE checkxsignals=TRUE checkothers=TRUE
MatchedLengths RGMII1 [InxSignalClass('RGMII1')] p11: tolerance=2.5 checknetsindiffpair=FALSE checkdiffpairvsdiffpair=TRUE checkxsignals=TRUE checkothers=TRUE
MatchedLengths RGMII2 [InNetClass('RGMII2')] p12: tolerance=2.5 checknetsindiffpair=FALSE checkdiffpairvsdiffpair=TRUE checkxsignals=TRUE checkothers=TRUE
MatchedLengths ETH [InNetClass('ETH_DIFF')] p13: tolerance=50 checknetsindiffpair=FALSE checkdiffpairvsdiffpair=TRUE checkxsignals=TRUE checkothers=TRUE
MinimumSolderMaskSliver [All] p1: minsoldermaskwidth=0
NetAntennae "Plating Bar" [(ObjectKind = 'Via') And (AsMM(Y1) = 0.6)] p1 off: netantennaetolerance=10
NetAntennae [All] p2 off: netantennaetolerance=0
NetAntennae NetAntennae_no_plating [All and not((ObjectKind = 'Via') And (AsMM(Y1) = 0.6))] p3: netantennaetolerance=0
PlaneClearance "Power Plane" [OnLayer('Int5 (PWR)')  or    OnLayer('Int6 (PWR)')] p1 off: clearance=0.15
PlaneClearance "Power Plane_1" [All] p2 off: clearance=0.15
PlaneClearance [All] p3: clearance=0.178
PlaneConnect PlaneConnect_VIAS [Isvia] p1: planeconnectstyle=Direct reliefexpansion=0.508 reliefentries=4 reliefconductorwidth=0.254 reliefairgap=0.254
PlaneConnect PlaneConnect_VIAS_1 [Isvia] p2: planeconnectstyle=Direct reliefexpansion=0.508 reliefentries=4 reliefconductorwidth=0.254 reliefairgap=0.254
PlaneConnect "GND Plane Mounting Holes connection" [All] p3: planeconnectstyle=Direct reliefexpansion=0.3 reliefentries=4 reliefconductorwidth=0.3 reliefairgap=0.15
PolygonConnect PolygonConnectDirect [All] p1 off: connectstyle=Direct reliefconductorwidth=0.254 reliefentries=4 polygonreliefangle="90 Angle" airgapwidth=0.254
PolygonConnect PolygonConnect_Direct [All] p2: connectstyle=Direct reliefconductorwidth=0.254 reliefentries=4 polygonreliefangle="90 Angle" airgapwidth=0.254
PolygonConnect PolygonConnect_Via [Isvia] p3: connectstyle=Direct reliefconductorwidth=0.254 reliefentries=4 polygonreliefangle="90 Angle" airgapwidth=0.254
PolygonConnect PolygonConnectRelief [All] p4 off: connectstyle=Relief reliefconductorwidth=0.254 reliefentries=4 polygonreliefangle="90 Angle" airgapwidth=0.254
RoutingVias "Buried Via" [IsBuriedVia] p1: holewidth=0.2 width=0.4 viastyle="Through Hole" minholewidth=0.2 minwidth=0.4 maxholewidth=0.2 maxwidth=0.4
RoutingVias "Blind Via" [IsMicroVia] p2: holewidth=0.1 width=0.25 viastyle="Through Hole" minholewidth=0.1 minwidth=0.25 maxholewidth=0.1 maxwidth=0.25
RoutingVias "THT Via" [(StartLayer = 'Top Layer') and (StopLayer = 'Bottom Layer')] p3: holewidth=0.2 width=0.4 viastyle="Through Hole" minholewidth=0.2 minwidth=0.4 maxholewidth=0.2 maxwidth=0.4
ShortCircuit "X1 Pads without Net" [InComponent('X1') and IsPad and Not InNet('') vs IsMicroVia and (HoleSize = 0.1) and IsFree and (Y1 = 0.6)] p1: allowed=TRUE
ShortCircuit [All] p2: allowed=FALSE
SilkToSilkClearance [All] p1: silktosilkclearance=0.1
SilkToSolderMaskClearance SilkscreenOverComponentPads [IsPad] p1 off: minsilkscreentomaskgap=0.1 clearancetoexposedcopper=TRUE
SolderMaskExpansion [All] p1: expansion=0 istentingtop=FALSE
SupplyNets "Schematic Supply Nets_7" [InNet('+V_SODIMM')] p1: voltage=0.000
SupplyNets "Schematic Supply Nets_6" [InNet('+V2.5_ETH')] p2: voltage=0.000
SupplyNets "Schematic Supply Nets_5" [InNet('+V_LINO')] p3: voltage=0.000
SupplyNets "Schematic Supply Nets_4" [InNet('+V1.0_ETH')] p4: voltage=0.000
SupplyNets "Schematic Supply Nets_3" [InNet('+V3.3')] p5: voltage=0.000
SupplyNets "Schematic Supply Nets_2" [InNet('GND')] p6: voltage=0.000
SupplyNets "Schematic Supply Nets_1" [InNet('+V1.8')] p7: voltage=0.000
SupplyNets "Schematic Supply Nets" [InNet('+V1.8_ETH')] p8: voltage=0.000
UnRoutedNet [Not (IsMicroVia and (HoleSize = 0.1) and IsFree and (Y1 = 0.6)  )] p1: checkbadconnections=TRUE
Width Breakout_SoC [WithinRoom('Breakout SoC') and (OnLayer('Top Layer') or OnLayer('Mid 1'))] p1: maxlimit=0.3 minlimit=0.08 preferedwidth=0.098 toplayer_prefwidth=0.08 midlayer1_maxwidth=0.098 midlayer2_maxwidth=0.082 midlayer2_prefwidth=0.082 midlayer4_maxwidth=0.098 midlayer5_prefwidth=0.1 bottomlayer_maxwidth=0.095 bottomlayer_prefwidth=0.095 minimp=50.000000 maximp=50.000000 favimp=50.000000 checkconnectedcopper=TRUE
Width Breakout_SoC_Bottom [WithinRoom('Bottom_Breakout') and OnLayer('Bottom Layer')] p2: maxlimit=0.3 minlimit=0.08 preferedwidth=0.098 toplayer_maxwidth=0.095 toplayer_prefwidth=0.08 midlayer1_maxwidth=0.098 midlayer2_maxwidth=0.082 midlayer2_prefwidth=0.082 midlayer4_maxwidth=0.098 midlayer5_maxwidth=0.1 midlayer5_prefwidth=0.1 bottomlayer_prefwidth=0.08 minimp=50.000000 maximp=50.000000 favimp=50.000000 checkconnectedcopper=TRUE
Width Breakout_eMMC [WithinRoom('Breakout_eMMC_1') and OnLayer('Top Layer')] p3: maxlimit=0.3 minlimit=0.08 preferedwidth=0.098 toplayer_prefwidth=0.08 midlayer1_maxwidth=0.098 midlayer2_maxwidth=0.082 midlayer2_prefwidth=0.082 midlayer4_maxwidth=0.098 midlayer5_maxwidth=0.1 midlayer5_prefwidth=0.1 bottomlayer_maxwidth=0.095 bottomlayer_prefwidth=0.095 minimp=50.000000 maximp=50.000000 favimp=50.000000 checkconnectedcopper=TRUE
Width "Fiducial and Logo" [(InComponent('FID1') or  InComponent('FID2') or  InComponent('FID3') or  InComponent('FID4') or  InComponent('FID5') or  InComponent('FID6') or  InComponent('FID7') or  InComponent('FID8') or  InComponent('LOGO1'))] p4: maxlimit=0.254 minlimit=0.08 preferedwidth=0.1
Width Ethernet [InNetClass('RGMII') OR InNetClass('RGMII2')] p5 off: maxlimit=0.15 minlimit=0.09 preferedwidth=0.095 toplayer_minwidth=0.1 toplayer_prefwidth=0.15 midlayer1_minwidth=0.095 midlayer1_maxwidth=0.095 midlayer2_minwidth=0.095 midlayer2_maxwidth=0.095 midlayer4_maxwidth=0.09 midlayer4_prefwidth=0.09 midlayer5_maxwidth=0.09 midlayer5_prefwidth=0.09 bottomlayer_minwidth=0.1 bottomlayer_prefwidth=0.15 minimp=50.000000 maximp=50.000000 favimp=50.000000 checkconnectedcopper=TRUE
Width RAM [InNetClass('RAM')] p6: maxlimit=0.3 minlimit=0.1 preferedwidth=0.15 midlayer1_maxwidth=0.15 midlayer2_maxwidth=0.15 midlayer4_maxwidth=0.14 midlayer4_prefwidth=0.14 midlayer5_maxwidth=0.14 midlayer5_prefwidth=0.14 minimp=50.000000 maximp=50.000000 favimp=50.000000
Width Power [InNetClass('Power')] p7: maxlimit=2 minlimit=0.1 preferedwidth=0.3 checkconnectedcopper=TRUE
Width [All] p8: maxlimit=0.3 minlimit=0.09 preferedwidth=0.095 toplayer_minwidth=0.1 toplayer_prefwidth=0.15 midlayer1_minwidth=0.095 midlayer1_maxwidth=0.095 midlayer2_minwidth=0.095 midlayer2_maxwidth=0.095 midlayer4_maxwidth=0.09 midlayer4_prefwidth=0.09 midlayer5_maxwidth=0.09 midlayer5_prefwidth=0.09 bottomlayer_minwidth=0.1 bottomlayer_prefwidth=0.15 minimp=50.000000 maximp=50.000000 favimp=50.000000
8 further rules are at their usual default settings.

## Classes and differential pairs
net class LVDS_ODD: MSP_14/15_N MSP_14/15_P MSP_16/17_N MSP_16/17_P MSP_19/20_N MSP_19/20_P MSP_21/22_N MSP_21/22_P MSP_24/25_N MSP_24/25_P
net class LVDS: MSP_1/2_N MSP_1/2_P MSP_4/5_N MSP_4/5_P MSP_6/7_N MSP_6/7_P MSP_9/10_N MSP_9/10_P MSP_11/12_N MSP_11/12_P
net class PCIe: PCIE_1_CLK_N PCIE_1_CLK_P PCIE_1_L0_RX_N PCIE_1_L0_RX_P PCIE_1_L0_TX_N PCIE_1_L0_TX_P
net class MSP_DIFF: MSP_1/2_P MSP_4/5_P MSP_6/7_N MSP_9/10_N MSP_11/12_P MSP_14/15_P MSP_16/17_N MSP_19/20_N MSP_21/22_N MSP_24/25_P MSP_26/27_N MSP_29/30_N
differential pair class USB: MSP_33/34 MSP_35/36 PCIE_1_CLK PCIE_1_L0_RX PCIE_1_L0_TX USB_2_SSRX USB_2_SSTX
component class "Low Speed": C50 C51 OSC3 R50 R51 R52 X1 X11 X12 X21 X23 X26 X27 X29 X32
component class "High Speed": C35 C36 C37 C38 C39 C40 C41 C42 C43 C44 C45 C46 C47 C48 C49 IC9 R48 R49
net class WiFi_CTRL: WiFi_BT_WKUP_DEV WiFi_BT_WKUP_HOST WiFi_LTE_COEX_IN WiFi_LTE_COEX_OUT WiFi_W_WKUP_DEV WiFi_W_WKUP_HOST
net class WiFi_Audio: PCM_CLK PCM_DIN PCM_DOUT PCM_MCLK PCM_SYNC
net class WiFi_UART: UART_1_CTS UART_1_RTS UART_1_RXD UART_1_TXD
component class "SoC SD eMMC and ETH": R13 R14 R15 R16 R17 R18 R22
net class ETH_DIFF: ETH_1_MDI0_N ETH_1_MDI0_P ETH_1_MDI1_N ETH_1_MDI1_P ETH_1_MDI2_N ETH_1_MDI2_P ETH_1_MDI3_N ETH_1_MDI3_P
net class CSI_1: CSI_1_CLK_N CSI_1_CLK_P CSI_1_D0_N CSI_1_D0_P CSI_1_D1_N CSI_1_D1_P
net class DSI: DSI_1_CLK_N DSI_1_CLK_P DSI_1_D0_N DSI_1_D0_P DSI_1_D1_N DSI_1_D1_P DSI_1_D2_N DSI_1_D2_P DSI_1_D3_N DSI_1_D3_P
component class Main: FID1 FID2 FID3 FID4 FID5 FID6 FID7 FID8
net class SD_Card: SD_1_CLK SD_1_CMD SD_1_D0 SD_1_D1 SD_1_D2 SD_1_D3
net class WiFi_SDIO: SD_2_CLK SD_2_CMD SD_2_D0 SD_2_D1 SD_2_D2 SD_2_D3
net class RGMII2: ETH_2_RGMII_RX_CTL ETH_2_RGMII_RXC ETH_2_RGMII_RXD0 ETH_2_RGMII_RXD1 ETH_2_RGMII_RXD2 ETH_2_RGMII_RXD3 ETH_2_RGMII_TX_CTL ETH_2_RGMII_TXC ETH_2_RGMII_TXD0 ETH_2_RGMII_TXD1 ETH_2_RGMII_TXD2 ETH_2_RGMII_TXD3
net class RGMII: ENET1_RD0 ENET1_RD1 ENET1_RD2 ENET1_RD3 ENET1_RX_CTL ENET1_RXC ENET1_TD0 ENET1_TD1 ENET1_TD2 ENET1_TD3 ENET1_TX_CTL ENET1_TXC
net class HS_DIFF_100: CSI_1_CLK_N CSI_1_CLK_P CSI_1_D0_N CSI_1_D0_P CSI_1_D1_N CSI_1_D1_P DSI_1_CLK_N DSI_1_CLK_P DSI_1_D0_N DSI_1_D0_P DSI_1_D1_N DSI_1_D1_P DSI_1_D2_N DSI_1_D2_P DSI_1_D3_N DSI_1_D3_P ETH_1_MDI0_N ETH_1_MDI0_P ETH_1_MDI1_N ETH_1_MDI1_P ETH_1_MDI2_N ETH_1_MDI2_P ETH_1_MDI3_N ETH_1_MDI3_P MSP_1/2_N MSP_1/2_P MSP_4/5_N MSP_4/5_P MSP_6/7_N MSP_6/7_P MSP_9/10_N MSP_9/10_P MSP_11/12_N MSP_11/12_P MSP_14/15_N MSP_14/15_P MSP_16/17_N MSP_16/17_P MSP_19/20_N MSP_19/20_P MSP_21/22_N MSP_21/22_P MSP_24/25_N MSP_24/25_P MSP_26/27_N MSP_26/27_P MSP_29/30_N MSP_29/30_P PCIE_1_CLK_N PCIE_1_CLK_P
net class HS_DIFF_90: MSP_33/34_N MSP_33/34_P MSP_35/36_N MSP_35/36_P PCIE_1_L0_RX_N PCIE_1_L0_RX_P PCIE_1_L0_TX_N PCIE_1_L0_TX_P USB_1_D_N USB_1_D_P USB_2_D_N USB_2_D_P USB_2_SSRX_N USB_2_SSRX_P USB_2_SSTX_N USB_2_SSTX_P
component class "SoC Power": C16 C17 C19 C20 C21 C22 C23 C24 C25 C26 C27 C28 C29
component class ETH_PHY: C127 C129 C130 C131 C132 C135 C136 C137 C138 C140 C142 C144 C145 C146 C147 C148 IC17 R86 R88 R89 R90 R91 R93 R94 R95
net class Power: +V1.0_ETH +V1.8 +V2.5_ETH +V3.3 +V_LINO +V_SODIMM GND
net class NC: NetIC3_E10 NetIC3_F10
differential pair USB_2_SSTX: +USB_2_SSTX_P -USB_2_SSTX_N
differential pair USB_2_SSRX: +USB_2_SSRX_P -USB_2_SSRX_N
differential pair PCIE_1_L0_TX: +PCIE_1_L0_TX_P -PCIE_1_L0_TX_N
differential pair PCIE_1_L0_RX: +PCIE_1_L0_RX_P -PCIE_1_L0_RX_N
differential pair PCIE_1_CLK: +PCIE_1_CLK_P -PCIE_1_CLK_N
differential pair MSP_35/36: +MSP_35/36_P -MSP_35/36_N
differential pair MSP_33/34: +MSP_33/34_P -MSP_33/34_N
differential pair MSP_29/30: +MSP_29/30_P -MSP_29/30_N
differential pair MSP_26/27: +MSP_26/27_P -MSP_26/27_N
differential pair MSP_24/25: +MSP_24/25_P -MSP_24/25_N
differential pair MSP_21/22: +MSP_21/22_P -MSP_21/22_N
differential pair MSP_19/20: +MSP_19/20_P -MSP_19/20_N
differential pair MSP_16/17: +MSP_16/17_P -MSP_16/17_N
differential pair MSP_14/15: +MSP_14/15_P -MSP_14/15_N
differential pair MSP_11/12: +MSP_11/12_P -MSP_11/12_N
differential pair MSP_9/10: +MSP_9/10_P -MSP_9/10_N
differential pair MSP_6/7: +MSP_6/7_P -MSP_6/7_N
differential pair MSP_4/5: +MSP_4/5_P -MSP_4/5_N
differential pair MSP_1/2: +MSP_1/2_P -MSP_1/2_N
differential pair DSI_1_D3: +DSI_1_D3_P -DSI_1_D3_N
differential pair DSI_1_D2: +DSI_1_D2_P -DSI_1_D2_N
differential pair DSI_1_D1: +DSI_1_D1_P -DSI_1_D1_N
differential pair DSI_1_D0: +DSI_1_D0_P -DSI_1_D0_N
differential pair DSI_1_CLK: +DSI_1_CLK_P -DSI_1_CLK_N
differential pair USB_2_D: +USB_2_D_P -USB_2_D_N
differential pair USB_1_D: +USB_1_D_P -USB_1_D_N
differential pair ETH_1_MDI3: +ETH_1_MDI3_P -ETH_1_MDI3_N
differential pair ETH_1_MDI2: +ETH_1_MDI2_P -ETH_1_MDI2_N
differential pair ETH_1_MDI1: +ETH_1_MDI1_P -ETH_1_MDI1_N
differential pair ETH_1_MDI0: +ETH_1_MDI0_P -ETH_1_MDI0_N
differential pair CSI_1_D1: +CSI_1_D1_P -CSI_1_D1_N
differential pair CSI_1_D0: +CSI_1_D0_P -CSI_1_D0_N
differential pair CSI_1_CLK: +CSI_1_CLK_P -CSI_1_CLK_N

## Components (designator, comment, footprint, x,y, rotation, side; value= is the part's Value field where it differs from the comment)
C1 "C-X5R-10u-6.3V-20%-0402" CAPC100X50X60L25L 7.332,21.86 r0 bottom value=10µF
C2 "C-X5R-2.2u-16V-20%-0402" CAPC100X50X60L25L 8.17,19.65 r180 bottom value=2.2µF
C3 "C-X5R-2.2u-16V-20%-0402" CAPC100X50X60L25L 8.17,20.96 r180 bottom value=2.2µF
C4 "C-X7R-10n-10V-10%-0201" CAPC60X30X33L15L 8.27,18.94 r180 top value=10nF
C5 "C-X7R-10n-10V-10%-0201" CAPC60X30X33L15L 8.27,19.54 r180 top value=10nF
C6 "C-X5R-10u-6.3V-20%-0402" CAPC100X50X60L25L 6.281,18.825 r0 top value=10µF
C7 "C-X5R-1u-6.3V-20%-0201" CAPC60X30X33L15L 6.202,19.575 r0 top value=1µF
C8 "C-X5R-1u-6.3V-20%-0201" CAPC60X30X33L15L 9.12,19.287 r90 top value=1µF
C9 "C-X5R-1u-6.3V-20%-0201" CAPC60X30X33L15L 13.35,21.37 r270 bottom value=1µF
C10 "C-X5R-220n-6.3V-20%-0201" CAPC60X30X33L15L 3.86,16.208 r270 top value=220nF
C11 "C-X5R-220n-6.3V-20%-0201" CAPC60X30X33L15L 34.735,32.13 r270 bottom value=220nF
C12 "C-X5R-220n-6.3V-20%-0201" CAPC60X30X33L15L 36.23,32.13 r270 bottom value=220nF
C13 "C-NP0-12p-25V-5%-0201" CAPC60X30X33L15L 64.813,7.98 r180 top value=12pF
C14 "C-NP0-12p-25V-5%-0201" CAPC60X30X33L15L 64.779,12.995 r180 top value=12pF
C15 "C-X5R-100n-6.3V-10%-0201" CAPC60X30X33L15L 14.916,9.736 r180 top value=100nF
C16 "C-NP0-100p-25V-5%-0201" CAPC60X30X33L15L 65.51,5.697 r270 top value=100pF
C17 "C-NP0-100p-25V-5%-0201" CAPC60X30X33L15L 64.66,5.242 r0 top value=100pF
C18 "C-NP0-100p-25V-5%-0201" CAPC60X30X33L15L 64.66,4.642 r0 top value=100pF
C19 "C-NP0-100p-25V-5%-0201" CAPC60X30X33L15L 17.441,18.438 r90 top value=100pF
C20 "C-X5R-22u-6.3V-20%-0805" CAPC200X125X100L50N 12.266,19.018 r180 top value=22µF
C21 "C-X5R-100n-6.3V-10%-0201" CAPC60X30X33L15L 18.666,11.883 r270 top value=100nF
C22 "C-X5R-10u-10V-20%-0603" CAPC160X80X90L35N 15.216,16.385 r180 top value=10µF
C23 "C-X5R-10u-10V-20%-0603" CAPC160X80X90L35N 17.816,7.398 r90 top value=10µF
C24 "C-X5R-10u-10V-20%-0603" CAPC160X80X90L35N 19.041,7.398 r90 top value=10µF
C25 "C-X5R-10u-10V-20%-0603" CAPC160X80X90L35N 21.09,6.43 r0 top value=10µF
C26 "C-NP0-100p-25V-5%-0201" CAPC60X30X33L15L 60.616,21.313 r180 top value=100pF
C27 "C-X5R-22u-6.3V-20%-0805" CAPC200X125X100L50N 61.25,18.277 r270 top value=22µF
C28 "C-X5R-100n-6.3V-10%-0201" CAPC60X30X33L15L 56.8,5 r270 bottom value=100nF
C29 "C-X5R-10u-10V-20%-0603" CAPC160X80X90L35N 64.078,21.189 r270 top value=10µF
C30 "C-X5R-1u-6.3V-20%-0201" CAPC60X30X33L15L 65.165,14.989 r180 top value=1µF
C31 "C-X5R-1u-6.3V-20%-0201" CAPC60X30X33L15L 65.154,17.189 r180 top value=1µF
C32 "C-X5R-1u-6.3V-20%-0201" CAPC60X30X33L15L 57.597,7.761 r0 bottom value=1µF
C33 "C-X5R-1u-6.3V-20%-0201" CAPC60X30X33L15L 57.592,9.961 r180 bottom value=1µF
C34 "C-X5R-10u-10V-20%-0603" CAPC160X80X90L35N 66.077,23.023 r180 top value=10µF
C35 "C-NP0-100p-25V-5%-0201" CAPC60X30X33L15L 43.75,23.25 r0 bottom value=100pF
C36 "C-NP0-100p-25V-5%-0201" CAPC60X30X33L15L 24.17,4.6 r270 bottom value=100pF
C37 "C-NP0-100p-25V-5%-0201" CAPC60X30X33L15L 43.75,21 r0 bottom value=100pF
C38 "C-NP0-100p-25V-5%-0201" CAPC60X30X33L15L 27.17,4.5 r270 bottom value=100pF
C39 "C-NP0-100p-25V-5%-0201" CAPC60X30X33L15L 43.77,18.75 r0 bottom value=100pF
C40 "C-NP0-100p-25V-5%-0201" CAPC60X30X33L15L 30.09,4.5 r270 bottom value=100pF
C41 "C-NP0-100p-25V-5%-0201" CAPC60X30X33L15L 43.76,15.75 r0 bottom value=100pF
C42 "C-NP0-100p-25V-5%-0201" CAPC60X30X33L15L 33.17,4.5 r270 bottom value=100pF
C43 "C-NP0-100p-25V-5%-0201" CAPC60X30X33L15L 45.2,13.5 r180 bottom value=100pF
C44 "C-NP0-100p-25V-5%-0201" CAPC60X30X33L15L 36.17,4.5 r270 bottom value=100pF
C45 "C-NP0-100p-25V-5%-0201" CAPC60X30X33L15L 50.89,13.04 r270 top value=100pF
C46 "C-NP0-100p-25V-5%-0201" CAPC60X30X33L15L 41.15,4.83 r270 bottom value=100pF
C47 "C-X5R-100n-6.3V-10%-0201" CAPC60X30X33L15L 55.15,24.24 r90 bottom value=100nF
C48 "C-X5R-100n-6.3V-10%-0201" CAPC60X30X33L15L 61.3,24.23 r90 bottom value=100nF
C49 "C-X5R-100n-6.3V-10%-0201" CAPC60X30X33L15L 58.14,26.57 r0 bottom value=100nF
C50 "C-X5R-100n-6.3V-10%-0201" CAPC60X30X33L15L 23.93,7.9 r270 bottom value=100nF
C51 "C-X5R-100n-6.3V-10%-0201" CAPC60X30X33L15L 10.885,6.1 r90 bottom value=100nF
C124 "C-NP0-22p-25V-5%-0201" CAPC60X30X33L15L 61.92,6.342 r90 top value=22pF
C125 "C-X7R-10n-10V-10%-0201" CAPC60X30X33L15L 62.72,4.642 r0 top value=10nF
C126 "C-X7R-10n-10V-10%-0201" CAPC60X30X33L15L 61.62,4.642 r180 top value=10nF
C127 "C-X5R-1u-6.3V-20%-0201" CAPC60X30X33L15L 60.99,6.342 r90 top value=1µF
C128 "C-X5R-1u-6.3V-20%-0201" CAPC60X30X33L15L 56.75,6.342 r90 top value=1µF
C129 "C-X5R-10u-6.3V-20%-0402" CAPC100X50X60L25L 58.1,6.042 r90 top value=10µF
C130 "C-X5R-100n-6.3V-10%-0201" CAPC60X30X33L15L 57.35,6.342 r90 top value=100nF
C131 "C-X5R-100n-6.3V-10%-0201" CAPC60X30X33L15L 60.36,6.342 r90 top value=100nF
C132 "C-X5R-100n-6.3V-10%-0201" CAPC60X30X33L15L 63.24,6.69 r90 top value=100nF
C133 "C-X5R-100n-6.3V-10%-0201" CAPC60X30X33L15L 55.55,6.342 r90 top value=100nF
C134 "C-X5R-1u-6.3V-20%-0201" CAPC60X30X33L15L 63.84,6.69 r90 top value=1µF
C135 "C-X5R-10u-6.3V-20%-0402" CAPC100X50X60L25L 64.59,6.402 r90 top value=10µF
C136 "C-X5R-10u-6.3V-20%-0402" CAPC100X50X60L25L 61.42,13.02 r0 bottom value=10µF
C137 "C-X5R-100n-6.3V-10%-0201" CAPC60X30X33L15L 54.075,11.37 r0 top value=100nF
C138 "C-X5R-100n-6.3V-10%-0201" CAPC60X30X33L15L 58.85,6.342 r90 top value=100nF
C139 "C-X5R-100n-6.3V-10%-0201" CAPC60X30X33L15L 58.8,16.4 r270 top value=100nF
C140 "C-X5R-100n-6.3V-10%-0201" CAPC60X30X33L15L 54.075,11.97 r0 top value=100nF
C141 "C-X5R-100n-6.3V-10%-0201" CAPC60X30X33L15L 59.4,16.4 r270 top value=100nF
C142 "C-X5R-100n-6.3V-10%-0201" CAPC60X30X33L15L 61.09,11.25 r0 bottom value=100nF
C143 "C-X5R-1u-6.3V-20%-0201" CAPC60X30X33L15L 56.15,6.342 r90 top value=1µF
C144 "C-X5R-1u-6.3V-20%-0201" CAPC60X30X33L15L 54.075,12.57 r0 top value=1µF
C145 "C-X5R-1u-6.3V-20%-0201" CAPC60X30X33L15L 61.31,12.27 r0 bottom value=1µF
C146 "C-X5R-1u-6.3V-20%-0201" CAPC60X30X33L15L 60,16.4 r270 top value=1µF
C147 "C-X5R-10u-6.3V-20%-0402" CAPC100X50X60L25L 65.503,13.967 r180 top value=10µF
C148 "C-X5R-100n-6.3V-10%-0201" CAPC60X30X33L15L 63.663,13.845 r90 top value=100nF
C173 "C-X5R-1u-6.3V-20%-0201" CAPC60X30X33L15L 58.2,16.4 r270 top value=1µF
C174 "C-X5R-1u-6.3V-20%-0201" CAPC60X30X33L15L 59.45,6.342 r90 top value=1µF
C175 "C-X5R-1u-6.3V-20%-0201" CAPC60X30X33L15L 54.075,10.77 r0 top value=1µF
C176 "C-X5R-1u-6.3V-20%-0201" CAPC60X30X33L15L 64.353,13.845 r90 top value=1µF
FID1 "MECH-Fiducial" MECH-Fiducial_Round 1,34 r90 bottom locked
FID2 "MECH-Fiducial" MECH-Fiducial_Round 68.6,34 r90 bottom locked
FID3 "MECH-Fiducial" MECH-Fiducial_Round 64.5,9 r90 bottom locked
FID4 "MECH-Fiducial" MECH-Fiducial_Round 4,5.5 r90 bottom locked
FID5 "MECH-Fiducial" MECH-Fiducial_Round 68.6,34 r90 top locked
FID6 "MECH-Fiducial" MECH-Fiducial_Round 1,34 r90 top locked
FID7 "MECH-Fiducial" MECH-Fiducial_Round 68,10 r90 top locked
FID8 "MECH-Fiducial" MECH-Fiducial_Round 4,5.5 r90 top locked
IC1 "IC_UBLOX_MAYA-W260-00B" UBLOX_MAYA-W1/W2 10.15,27.55 r0 top locked
IC2 "IC-TI-TCA9543APWR" TSSOP14P65_440X500X120L60X25 5.825,11.912 r90 top
IC3 "NXP-PCAL6416AHF-HVQFN24" QFN24P50_400X400X80L40X20T200X200L_SoM 35.17,28.422 r180 bottom
IC4 "IC-TI-INA219BIDR" SOIC8P127_500X600X175L100X40_no_Silkscreen 14.53,12.907 r0 top
IC5 "TI-TPS62A02DRLR" SOT563-6P50_160X60L30N 15.216,18.073 r0 top
IC6 "TI-TPS62A02DRLR" SOT563-6P50_160X60L30N 62.39,21.227 r90 top
IC7 "IC-TI-TLV75510PDQNR" X2SON4P65_100X100X40L36X21T48X48-1x1mm 65.195,16.089 r90 top
IC8 "TI-TLV75525PDQNR" X2SON4P65_100X100X40L36X21T48X48-1x1mm 57.625,8.861 r90 bottom
IC9 "IC-TI-TMUXHS4212IRKS" QFN20P50-250X450X100L40X25T100X300L 58.17,24.2 r270 bottom
IC17 "TI-DP83867IRRGZR" "QFN48P50_700X700X100L60X24T410X410 - SoM" 59.075,11.175 r90 top locked
L1 "L-TAYIO-MBMK2520T1R0M" INDC1008X40N 12.266,16.955 r180 top value=1µH
L2 "L-TAYIO-MBMK2520T1R0M" INDC1008X40N 63.25,18.249 r270 top value=1µH
MECH1 "MECH-Wurth-9774015243R" MECH-Wurth-9774015243R-Shaved-Pad-for-Lino 47.3,32.5 r0 top locked
OSC1 "OSC-QANTEK-QC3225.0000H47R3" OSC-SMD-3.2mmx2.5mm 64.811,10.487 r90 top value="25 MHz"
OSC2 "OSC-TI-CDC6CE025000ADLFR" "OSC-SMD-2.5mmx2.0mm - SOM" 25.85,7.4 r180 bottom
OSC3 "OSC-Epson-SG-210STF 24.5760ML0-24.576MHz-50ppm-2.5x2mm" T_Abracon_ASDMB-24.000MHZ-LC-T 12.61,5.543 r270 bottom value=24.576MHz
Q3 "2N MOSFET" SOT563-6P50_160X60L30N 52.16,7.345 r90 top
R1 "R-0R-50mW-5%-0201" RESC60X30X33L15L 16.7,30.325 r0 top value=0
R2 "R-0R-50mW-5%-0201" RESC60X30X33L15L 16.7,29.237 r0 top value=0
R3 "R-100K-50mW-1%-0201" RESC60X30X33L15L 3.85,27.61 r0 top value=100k
R4 "R-100K-50mW-1%-0201" RESC60X30X33L15L 3.85,28.21 r0 top value=100k
R5 "R-100K-50mW-1%-0201" RESC60X30X33L15L 3.85,25.76 r0 top value=100k
R6 "R-100K-50mW-1%-0201" RESC60X30X33L15L 3.85,24.71 r0 top value=100k
R7 "R-100K-50mW-1%-0201" RESC60X30X33L15L 16.45,24.27 r270 top value=100k
R8 "R-100K-50mW-1%-0201" RESC60X30X33L15L 16.45,25.421 r90 top value=100k
R9 "R-0R-50mW-5%-0201" RESC60X30X33L15L 4.733,17.658 r180 top value=0
R10 "R-0R-50mW-5%-0201" RESC60X30X33L15L 4.733,17.058 r180 top value=0
R11 "R-2.2K-50mW-5%-0201" RESC60X30X33L15L 4.46,16.208 r90 top value=2.2k
R12 "R-2.2K-50mW-5%-0201" RESC60X30X33L15L 5.06,16.208 r90 top value=2.2k
R13 "R-100K-50mW-1%-0201" RESC60X30X33L15L 6.45,7.47 r90 top value=100k
R14 "R-100K-50mW-1%-0201" RESC60X30X33L15L 7.05,7.47 r90 top value=100k
R15 "R-10K-50mW-1%-0201" RESC60X30X33L15L 5.85,7.47 r270 top value=10k
R16 "R-2.2K-50mW-5%-0201" RESC60X30X33L15L 7.08,16.208 r90 top value=2.2k
R17 "R-2.2K-50mW-5%-0201" RESC60X30X33L15L 6.48,16.208 r90 top value=2.2k
R18 "R-10K-50mW-1%-0201" RESC60X30X33L15L 7.68,16.208 r90 top value=10k
R19 "R-0R-50mW-5%-0201" RESC60X30X33L15L 5.871,17.058 r0 top value=0
R20 "R-0R-50mW-5%-0201" RESC60X30X33L15L 5.871,16.208 r270 top value=0
R21 "R-100K-50mW-1%-0201" RESC60X30X33L15L 39.25,28.5 r180 bottom value=100k
R22 "R-10K-50mW-1%-0201" RESC60X30X33L15L 35.51,32.13 r90 bottom value=10k
R24 "R-10K-50mW-1%-0201" RESC60X30X33L15L 39.25,27.75 r0 bottom value=10k
R25 "R-0R-50mW-5%-0201" RESC60X30X33L15L 63.706,7.98 r180 top value=0
R26 "R-2.2K-50mW-5%-0201" RESC60X30X33L15L 8.53,17.112 r180 top value=2.2k
R27 "R-2.2K-50mW-5%-0201" RESC60X30X33L15L 8.812,9.821 r270 top value=2.2k
R28 "R-0R-50mW-5%-0201" RESC60X30X33L15L 8.53,17.712 r0 top value=0
R29 "R-2.2K-50mW-5%-0201" RESC60X30X33L15L 8.53,16.512 r180 top value=2.2k
R30 "R-2.2K-50mW-5%-0201" RESC60X30X33L15L 9.789,14.808 r180 top value=2.2k
R31 "R-0R-50mW-5%-0201" RESC60X30X33L15L 8.53,15.896 r0 top value=0
R32 "R-0R-50mW-5%-0201" RESC60X30X33L15L 9.789,15.408 r180 top value=0
R33 "R-0R-50mW-5%-0201" RESC60X30X33L15L 9.789,16.008 r180 top value=0
R34 "R-0R-50mW-5%-0201" RESC60X30X33L15L 9.789,17.208 r180 top value=0
R35 "R-0R-50mW-5%-0201" RESC60X30X33L15L 9.789,16.608 r180 top value=0
R36 "R-10R-50mW-5%-0201" RESC60X30X33L15L 13.787,9.736 r0 top value=10
R37 "R-10R-50mW-5%-0201" RESC60X30X33L15L 16.019,9.736 r180 top value=10
R38 "R-453K-50mW-1%-0201" RESC60X30X33L15L 16.841,18.438 r90 top value=453k
R39 "R-100K-50mW-1%-0201" RESC60X30X33L15L 15.147,19.553 r0 top value=100k
R40 "R-VISHAY-WSK1206R0100FEA18" RESSC320X160X65L60N 14.788,8.193 r180 top value=10m
R41 "R-200K-50mW-1%-0201" RESC60X30X33L15L 60.306,20.452 r270 top value=200k
R42 "R-100K-50mW-1%-0201" RESC60X30X33L15L 60.91,20.463 r90 top value=100k
R43 "R-1M-50mW-5%-0201" RESC60X30X33L15L 62.204,24.552 r270 top value=1M
R44 "R-1M-50mW-5%-0201" RESC60X30X33L15L 62.204,25.667 r270 top value=1M
R45 "R-1M-50mW-5%-0201" RESC60X30X33L15L 62.204,23.452 r90 top value=1M
R46 "R-2.2K-50mW-5%-0201" RESC60X30X33L15L 64.214,23.313 r180 top value=2.2k
R47 "R-1M-50mW-5%-0201" RESC60X30X33L15L 63.07,23.313 r0 top value=1M
R48 "R-10K-50mW-1%-0201" RESC60X30X33L15L 61.34,25.35 r270 bottom value=10k
R49 "R-10K-50mW-1%-0201" RESC60X30X33L15L 56.11,26.58 r0 bottom value=10k
R50 "R-100K-50mW-1%-0201" RESC60X30X33L15L 36.89,32.13 r90 bottom value=100k
R51 "R-22R-50mW-5%-0201" RESC60X30X33L15L 23.93,6.477 r270 bottom value=22
R52 "R-22R-50mW-5%-0201" RESC60X30X33L15L 10.885,4.5 r270 bottom value=22
R53 "R-0R-50mW-5%-0201" RESC60X30X33L15L 61.34,26.45 r270 bottom value=0
R82 "R-1K-50mW-5%-0201" RESC60X30X33L15L 62.19,10.88 r90 bottom value=1k
R83 "R-10K-50mW-1%-0201" RESC60X30X33L15L 57,16.4 r90 top value=10k
R84 "R-5.76K-50mW-1%-0201" RESC60X30X33L15L 56.4,16.4 r90 top value=5.76k
R85 "R-5.76K-50mW-1%-0201" RESC60X30X33L15L 54.85,15.96 r90 top value=5.76k
R86 "R-2.49K-50mW-1%-0201" RESC60X30X33L15L 57.6,16.4 r270 top value=2.49k
R87 "R-2.49K-50mW-1%-0201" RESC60X30X33L15L 55.8,16.4 r270 top value=2.49k
R88 "R-2.49K-50mW-1%-0201" RESC60X30X33L15L 54,15.37 r0 top value=2.49k
R89 "R-5.76K-50mW-1%-0201" RESC60X30X33L15L 54.075,6.27 r180 top value=5.76k
R90 "R-10K-50mW-1%-0201" RESC60X30X33L15L 54.075,8.07 r180 top value=10k
R91 "R-5.76K-50mW-1%-0201" RESC60X30X33L15L 54.075,8.67 r180 top value=5.76k
R93 "R-5.76K-50mW-1%-0201" RESC60X30X33L15L 54.25,14.52 r90 top value=5.76k
R94 "R-5.76K-50mW-1%-0201" RESC60X30X33L15L 54.25,13.42 r270 top value=5.76k
R95 "R-2.49K-50mW-1%-0201" RESC60X30X33L15L 54.075,6.87 r0 top value=2.49k
R96 "R-2.49K-50mW-1%-0201" RESC60X30X33L15L 54.075,7.47 r0 top value=2.49k
R97 "R-2.49K-50mW-1%-0201" RESC60X30X33L15L 54.075,9.27 r0 top value=2.49k
R98 "R-2.49K-50mW-1%-0201" RESC60X30X33L15L 53.65,14.52 r270 top value=2.49k
R123 "R-2.49K-50mW-1%-0201" RESC60X30X33L15L 53.65,13.42 r90 top value=2.49k
R124 "R-11K-50mW-1%-0201" RESC60X30X33L15L 62.52,6.342 r90 top value=11k
SW1 "CON-TE-Connectivity-EDS01SGRSTR04Q-6-2319848-4" CON-TE-Connectivity-EDS01SGRSTR04Q-6-2319848-4 59.21,29.52 r180 top locked
T1 "T-ONSEMI-NTZD3154NT1G" SOT563-6P50_160X60L30N 9.55,11.833 r270 top
T2 "T-ONSEMI-NTZD3154NT1G" SOT563-6P50_160X60L30N 63.579,24.938 r270 top
T3 "T-ONSEMI-NTZD3154NT1G" SOT563-6P50_160X60L30N 65.939,24.961 r90 top
TP1 "#TestPin_SMD-1.5x2.2mm#_NoPaste" TESTPIN/2.20x1.50 7,33.7 r270 bottom locked
TP2 "#TestPin_SMD-1.5x2.2mm#_NoPaste" TESTPIN/2.20x1.50 9.54,33.7 r270 bottom locked
TP3 "#TestPin_SMD-1.5x2.2mm#_NoPaste" TESTPIN/2.20x1.50 12.08,33.7 r270 bottom locked
TP4 "#TestPin_SMD-1.5x2.2mm#_NoPaste" TESTPIN/2.20x1.50 14.62,33.7 r270 bottom locked
TP5 "#TestPin_SMD-1.5x2.2mm#_NoPaste" TESTPIN/2.20x1.50 17.16,33.7 r270 bottom locked
TP6 "#TestPin_SMD-1.5x2.2mm#_NoPaste" TESTPIN/2.20x1.50 52.44,33.7 r270 bottom locked
TP7 "#TestPin_SMD-1.5x2.2mm#_NoPaste" TESTPIN/2.20x1.50 54.98,33.7 r270 bottom locked
TP8 "#TestPin_SMD-1.5x2.2mm#_NoPaste" TESTPIN/2.20x1.50 57.52,33.7 r270 bottom locked
TP9 "#TestPin_SMD-1.5x2.2mm#_NoPaste" TESTPIN/2.20x1.50 60.06,33.7 r270 bottom locked
TP10 "#TestPin_SMD-1.5x2.2mm#_NoPaste" TESTPIN/2.20x1.50 62.6,33.7 r270 bottom locked
TP11 "#TestPin_SMD-0.50mm#_NoPaste" Pad_SMT_Round_0.5_NoSilk_NoPaste 63.607,12.995 r90 top
TP12 "#TestPin_SMD-1.00mm#_NoPaste" Pad_SMT_1.0x1.0_NoPaste 9.787,9.816 r270 top
TP13 "#TestPin_SMD-1.00mm#_NoPaste" Pad_SMT_1.0x1.0_NoPaste 9.787,13.833 r270 top
TP14 "#TestPin_SMD-1.00mm#_NoPaste" Pad_SMT_1.0x1.0_NoPaste 65.951,20.707 r90 top
TP15 "#TestPin_SMD-1.00mm#_NoPaste" Pad_SMT_1.0x1.0_NoPaste 9.15,8.208 r90 top
TP16 "#TestPin_SMD-1.00mm#_NoPaste" Pad_SMT_1.0x1.0_NoPaste 11.726,9.407 r90 top
TP17 "#TestPin_SMD-1.00mm#_NoPaste" Pad_SMT_1.0x1.0_NoPaste 17.672,9.407 r90 top
TP18 "#TestPin_SMD-1.00mm#_NoPaste" Pad_SMT_1.0x1.0_NoPaste 60.23,25.44 r90 top
TP19 "#TestPin_SMD-1.00mm#_NoPaste" Pad_SMT_1.0x1.0_NoPaste 63.819,15.07 r90 top
TP20 "#TestPin_SMD-1.00mm#_NoPaste" Pad_SMT_1.0x1.0_NoPaste 65.951,18.164 r90 top
X1 "CON-SODIMM-DDR4-TEST" SODIMM_DDR4_no_Module 38.3,0 r0 top locked
X11 "CON-LINO-P-CARRIER" HIROSE_DF40C_100DS_LINO_CARRIER_PRIMARY 22.3,18.8 r270 top locked
X12 "CON-LINO-S-CARRIER" HIROSE_DF40C_100DS_LINO_CARRIER_SECONDARY 47.3,16.3 r270 top locked
X21 "CON-TE-Connectivity-1551573-5" TE-1551573-5 27.8,6.3 r180 top locked
X23 "CON-TE-Connectivity-1551573-5" TE-1551573-5 32.88,6.3 r180 top locked
X26 "CON-TE-Connectivity-1551573-5" TE-1551573-5 40.5,6.3 r0 top locked
X27 "CON-TE-Connectivity-1551573-5" TE-1551573-5 40.5,33.7 r0 top locked
X29 "CON-TE-Connectivity-1551573-5" TE-1551573-5 35.42,33.7 r0 top locked
X32 "CON-TE-Connectivity-1551573-5" TE-1551573-5 27.8,33.7 r180 top locked

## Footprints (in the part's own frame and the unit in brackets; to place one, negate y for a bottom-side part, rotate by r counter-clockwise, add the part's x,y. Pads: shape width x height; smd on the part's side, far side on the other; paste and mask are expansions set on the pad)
CAPC60X30X33L15L [mm] "SMT capacitor 0201, 0.33mm height, High density"
  rrect33% 0.3x0.3 smd paste+0 mask+0: 1(-0.3,0) 2(0.3,0)
  body extent -0.3,-0.15 0.3,0.15, height 0.31
CAPC100X50X60L25L [mm] "SMD capacitor 0402, 0.6mm height, High Density"
  rrect20% 0.5x0.6 smd paste+0: 1(-0.5,0)
  rrect20% 0.5x0.6 smd: 2(0.5,0)
  body extent -0.5,-0.25 0.5,0.25, height 0.6
CAPC160X80X90L35N [mm] "SMD capacitor 0603, 0.9mm height, Normal density"
  rrect20% 0.7x0.85 smd: 1(-0.775,0) 2(0.775,0)
  body extent -0.8,-0.4 0.8,0.4, height 0.9
CAPC200X125X100L50N [mm] "SMT capacitor 0805, 1mm height, Normal density"
  rrect20% 1x1.2 smd: 1(-0.95,0) 2(0.95,0)
  body extent -1,-0.62 1,0.63, height 1
CON-TE-Connectivity-EDS01SGRSTR04Q-6-2319848-4 [mm] "DIP Switch SPST 1x Surface Mount"
  rrect30% 2x1.1 smd: 1(-4.4,0) 2(4.4,0)
  silkscreen extent -4.04,0.87 -3.84,1.07, body extent -4.9,-1.22 4.9,1.22, height 2.8
HIROSE_DF40C_100DS_LINO_CARRIER_PRIMARY [mm]
  rect 0.2x1.14 smd paste-2539.97 mask-2539.97: P1(-9.8,-1.32) P2(-9.8,1.32) P3(-9.4,-1.32) P4(-9.4,1.32) P5(-9,-1.32) P6(-9,1.32) P7(-8.6,-1.32) P8(-8.6,1.32) P9(-8.2,-1.32) P10(-8.2,1.32) P11(-7.8,-1.32) P12(-7.8,1.32) P13(-7.4,-1.32) P14(-7.4,1.32) P15(-7,-1.32) P16(-7,1.32) P17(-6.6,-1.32) P18(-6.6,1.32) P19(-6.2,-1.32) P20(-6.2,1.32) P21(-5.8,-1.32) P22(-5.8,1.32) P23(-5.4,-1.32) P24(-5.4,1.32) P25(-5,-1.32) P26(-5,1.32) P27(-4.6,-1.32) P28(-4.6,1.32) P29(-4.2,-1.32) P30(-4.2,1.32) P31(-3.8,-1.32) P32(-3.8,1.32) P33(-3.4,-1.32) P34(-3.4,1.32) P35(-3,-1.32) P36(-3,1.32) P37(-2.6,-1.32) P38(-2.6,1.32) P39(-2.2,-1.32) P40(-2.2,1.32) P41(-1.8,-1.32) P42(-1.8,1.32) P43(-1.4,-1.32) P44(-1.4,1.32) P45(-1,-1.32) P46(-1,1.32) P47(-0.6,-1.32) P48(-0.6,1.32) P49(-0.2,-1.32) P50(-0.2,1.32) P51(0.2,-1.32) P52(0.2,1.32) P53(0.6,-1.32) P54(0.6,1.32) P55(1,-1.32) P56(1,1.32) P57(1.4,-1.32) P58(1.4,1.32) P59(1.8,-1.32) P60(1.8,1.32) P61(2.2,-1.32) P62(2.2,1.32) P63(2.6,-1.32) P64(2.6,1.32) P65(3,-1.32) P66(3,1.32) P67(3.4,-1.32) P68(3.4,1.32) P69(3.8,-1.32) P70(3.8,1.32) P71(4.2,-1.32) P72(4.2,1.32) P73(4.6,-1.32) P74(4.6,1.32) P75(5,-1.32) P76(5,1.32) P77(5.4,-1.32) P78(5.4,1.32) P79(5.8,-1.32) P80(5.8,1.32) P81(6.2,-1.32) P82(6.2,1.32) P83(6.6,-1.32) P84(6.6,1.32) P85(7,-1.32) P86(7,1.32) P87(7.4,-1.32) P88(7.4,1.32) P89(7.8,-1.32) P90(7.8,1.32) P91(8.2,-1.32) P92(8.2,1.32) P93(8.6,-1.32) P94(8.6,1.32) P95(9,-1.32) P96(9,1.32) P97(9.4,-1.32) P98(9.4,1.32) P99(9.8,-1.32) P100(9.8,1.32)
  silkscreen extent -11,-2.2 -10.8,-2, body extent -11.3,-1.69 11.3,1.69, height 1.45
HIROSE_DF40C_100DS_LINO_CARRIER_SECONDARY [mm]
  rect 0.2x1.14 smd paste-2539.97 mask-2539.97: S1(-9.8,-1.32) S2(-9.8,1.32) S3(-9.4,-1.32) S4(-9.4,1.32) S5(-9,-1.32) S6(-9,1.32) S7(-8.6,-1.32) S8(-8.6,1.32) S9(-8.2,-1.32) S10(-8.2,1.32) S11(-7.8,-1.32) S12(-7.8,1.32) S13(-7.4,-1.32) S14(-7.4,1.32) S15(-7,-1.32) S16(-7,1.32) S17(-6.6,-1.32) S18(-6.6,1.32) S19(-6.2,-1.32) S20(-6.2,1.32) S21(-5.8,-1.32) S22(-5.8,1.32) S23(-5.4,-1.32) S24(-5.4,1.32) S25(-5,-1.32) S26(-5,1.32) S27(-4.6,-1.32) S28(-4.6,1.32) S29(-4.2,-1.32) S30(-4.2,1.32) S31(-3.8,-1.32) S32(-3.8,1.32) S33(-3.4,-1.32) S34(-3.4,1.32) S35(-3,-1.32) S36(-3,1.32) S37(-2.6,-1.32) S38(-2.6,1.32) S39(-2.2,-1.32) S40(-2.2,1.32) S41(-1.8,-1.32) S42(-1.8,1.32) S43(-1.4,-1.32) S44(-1.4,1.32) S45(-1,-1.32) S46(-1,1.32) S47(-0.6,-1.32) S48(-0.6,1.32) S49(-0.2,-1.32) S50(-0.2,1.32) S51(0.2,-1.32) S52(0.2,1.32) S53(0.6,-1.32) S54(0.6,1.32) S55(1,-1.32) S56(1,1.32) S57(1.4,-1.32) S58(1.4,1.32) S59(1.8,-1.32) S60(1.8,1.32) S61(2.2,-1.32) S62(2.2,1.32) S63(2.6,-1.32) S64(2.6,1.32) S65(3,-1.32) S66(3,1.32) S67(3.4,-1.32) S68(3.4,1.32) S69(3.8,-1.32) S70(3.8,1.32) S71(4.2,-1.32) S72(4.2,1.32) S73(4.6,-1.32) S74(4.6,1.32) S75(5,-1.32) S76(5,1.32) S77(5.4,-1.32) S78(5.4,1.32) S79(5.8,-1.32) S80(5.8,1.32) S81(6.2,-1.32) S82(6.2,1.32) S83(6.6,-1.32) S84(6.6,1.32) S85(7,-1.32) S86(7,1.32) S87(7.4,-1.32) S88(7.4,1.32) S89(7.8,-1.32) S90(7.8,1.32) S91(8.2,-1.32) S92(8.2,1.32) S93(8.6,-1.32) S94(8.6,1.32) S95(9,-1.32) S96(9,1.32) S97(9.4,-1.32) S98(9.4,1.32) S99(9.8,-1.32) S100(9.8,1.32)
  silkscreen extent -11,-2.2 -10.8,-2, body extent -11.3,-1.69 11.3,1.69, height 1.45
INDC1008X40N [mm] "Ferrite Bead/Inductor 1008 (2520 metric), max height 1.2mm"
  rrect20% 0.8x2 smd: 1(-1,0) 2(1,0)
  body extent -1.25,-1 1.25,1, height 1.24
MECH-Fiducial_Round [mm] "Round fiducial, 1mm copper pad, 2mm total diameter"
  Top Layer region: -0.4,0 -0.37,0.153 -0.283,0.283 -0.153,0.37 0,0.4 0,0.4 0.153,0.37 0.283,0.283 0.37,0.153 0.4,0 0.4,0 0.37,-0.153 0.283,-0.283 0.153,-0.37 0,-0.4 0,-0.4 -0.153,-0.37 -0.283,-0.283 -0.37,-0.153 -0.4,0
  Top Layer keep-out region: -1,0 -0.924,0.383 -0.707,0.707 -0.383,0.924 0,1 0,1 0.383,0.924 0.707,0.707 0.924,0.383 1,0 1,0 0.924,-0.383 0.707,-0.707 0.383,-0.924 0,-1 0,-1 -0.383,-0.924 -0.707,-0.707 -0.924,-0.383 -1,0
MECH-Wurth-9774015243R-Shaved-Pad-for-Lino [mm]
  round 0.025 smd paste-5: 1(0,-0.225)
  round 1.3 / inner round 4 / far side round 4 hole 3 unplated: ""(0,0)
  Top Layer region: -1.477,2.2 -2.363,1.199 -2.648,-0.108 -2.258,-1.387 -1.294,-2.313 0,-2.65 1.294,-2.313 2.258,-1.386 2.648,-0.107 2.363,1.199 1.477,2.2 1.477,2.2 1.477,2.2
  body extent -2.16,-2.17 2.16,2.17, height 1.5
"OSC-SMD-2.5mmx2.0mm - SOM" [mm] "Created for CDC6CxxxxxxxxDLF"
  rrect20% 0.9x0.65 smd: 1(-0.75,0.825) 2(-0.75,-0.825) 3(0.75,-0.825) 4(0.75,0.825)
  body extent -1,-1.25 1,1.25, height 0.86
OSC-SMD-3.2mmx2.5mm [mm]
  rrect20% 1.4x1.2 smd: 1(-1.1,-0.8) 2(1.1,-0.8) 3(1.1,0.8) 4(-1.1,0.8)
  silkscreen extent -2.06,-1.65 2.06,1.65, body extent -1.65,-1.3 1.65,1.3, height 0.8
Pad_SMT_1.0x1.0_NoPaste [mm]
  rrect30% 1x1 smd paste-127 mask+0: 1(0,0)
Pad_SMT_Round_0.5_NoSilk_NoPaste [mm] "Removing Slikscreen from test point"
  round 0.5 smd paste-127 mask+0: 1(0,0)
QFN20P50-250X450X100L40X25T100X300L [mm] "QFN, 20-Leads, Body 4.5x2.5mm (max), Pitch 0.50mm, High Density"
  rrect20% 0.25x0.6 smd: 1(-0.25,2.15) 10(-0.25,-2.15) 11(0.25,-2.15) 20(0.25,2.15)
  rrect20% 0.6x0.25 smd: 2(-1.15,1.75) 3(-1.15,1.25) 4(-1.15,0.75) 5(-1.15,0.25) 6(-1.15,-0.25) 7(-1.15,-0.75) 8(-1.15,-1.25) 9(-1.15,-1.75) 12(1.15,-1.75) 13(1.15,-1.25) 14(1.15,-0.75) 15(1.15,-0.25) 16(1.15,0.25) 17(1.15,0.75) 18(1.15,1.25) 19(1.15,1.75)
  rrect10% 1x3 smd paste-2539.97: 21(0,0)
  body extent -1.3,-2.3 1.3,2.3, height 1
QFN24P50_400X400X80L40X20T200X200L_SoM [mm] "QFN24 0.5mm pitch, adopted for use in SoM design"
  rrect20% 0.9x0.25 smd: 1(-2.05,1.25) 2(-2.05,0.75) 3(-2.05,0.25) 4(-2.05,-0.25) 5(-2.05,-0.75) 6(-2.05,-1.25) 13(2.05,-1.25) 14(2.05,-0.75) 15(2.05,-0.25) 16(2.05,0.25) 17(2.05,0.75) 18(2.05,1.25)
  rrect20% 0.25x0.9 smd: 7(-1.25,-2.05) 8(-0.75,-2.05) 9(-0.25,-2.05) 10(0.25,-2.05) 11(0.75,-2.05) 12(1.25,-2.05) 19(1.25,2.05) 20(0.75,2.05) 21(0.25,2.05) 22(-0.25,2.05) 23(-0.75,2.05) 24(-1.25,2.05)
  rrect8% 2.1x2.1 smd paste-5: 25(0,0)
  rrect25% 0.7x0.7 on Bottom Paste mask+0.102: ""(-0.5,-0.5) ""(-0.5,0.5) ""(0.5,-0.5) ""(0.5,0.5)
  body extent -2.1,-2.1 2.1,2.1, height 0.8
